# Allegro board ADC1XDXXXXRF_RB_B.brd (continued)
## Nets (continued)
N16907762: C179.1 R90.2 R91.2 U13.8(FB2)
N16907804: C165.2 U13.9(BST2)
N16911166: C154.1 U12.17(VREGVCO)
N16911176: C321.1 U12.21(FOUT)
N16911178: C154.2 R78.2
N16911299: C155.2 U12.18(VREFVCO)
N16911375: C142.2 R70.1
N16911379: C142.1 U12.28(VREGPLL2)
N16911437: C143.1 U12.36(VREGDIG)
N16911467: C140.2 U12.32(OSCIN*)
N16911489: C149.2 U12.6(VREGBUF)
N16911507: C147.2 U12.26(VREGPLL1)
N16911511: C147.1 R71.1
N16915941: R66.2 R67.1 Y3.3(OUT)
N16917380: R73.1 U12.25(FLOUT)
N16922604: C343.2 T2.2
N16954745: C223.1(POS) C226.2 L12.1 R118.1 U20.5(OUTPUT)
N16954757: C227.1 U20.1(BYPASS)
N16954773: C226.1 R117.2 R118.2 U20.6(ADJ)
N17041129: R18.2 U2.99(RESET_N) U3.3(RESET_N)
N17122999: R20.2 U4.1(A0)
N17127467: R16.1 U2.85(PA3/WU2)
N17138281: C64.1(POS) C65.1 C66.1 L1.1 U2.10(AVCC1) U2.17(AVCC2)
N17209995: J12.2(A) L9.2
N17221364: C157.1(POS) L4.1 R99.2 SW2.2
N17237535: LD11.2(CATHODE) U2.82(PA0/INT0_N)
N17238039: LD11.1(ANODE) R142.1
N17247885: LD10.1(ANODE) R99.1
N17271500: C186.1 U15.1(BYPASS)
N17271514: C185.1 R97.2 R98.2 U15.6(ADJ)
N17272516: C230.1(POS) C233.2 L13.1 R125.1 U22.5(OUTPUT)
N17272520: C234.1 U22.1(BYPASS)
N17272540: C233.1 R124.2 R125.2 U22.6(ADJ)
N17383940: C70.1 U2.11(XTALOUT) Y1.1
N17383990: C71.1 U2.12(XTALIN) Y1.2
N17384219: TP2.1 U2.1(CLKOUT)
N17400918: R92.2 U23.20(RT)
N17401691: R93.2 U23.4(COMP)
N17402468: C235.1 U23.1(SS/TRK)
N17411980: C236.1 R93.1
N17414023: SW1.1 U3.4(MR_N)
N17421515: C237.1 U23.18(VCC)
N17425568: R94.2 R95.2 U23.2(FB)
N17434478: C238.2 D1.2(CATHODE) D5.2(CATHODE) L7.1 U23.7(SW1) U23.8(SW2) U23.13(SW3) U23.14(SW4)
N17462336: C197.1 C239.1(POS) L7.2 L8.1 R94.1
N17658689: C268.1 U1.K2(VBIASI2)
N17658690: C79.1 U1.M4(VBIASQ2)
N17663170: C73.1 U1.L2(VBIASQ1)
N17675090: C72.1 U1.J4(VBIASI1)
N17676120: TP1.1 U1.B1(VBG)
N17676520: R12.1 U1.C3(REXT+)
N17676524: R12.2 U1.D3(REXT-)
N17676530: R7.1 U1.C1(RTRIM+)
N17676534: R7.2 U1.D2(RTRIM-)
N17751700: J21.1 L9.4
N17752133: J21.2 SW2.3
N17824195: J12.1(C) L9.1
N17846912: R9.2 U1.U3(PDI)
N17848835: R25.2 U1.V3(PDQ)
N17849798: R2.2 U1.Y3(FSR)
N17850762: R3.2 U1.W4(DDRPHASE)
N17851727: R4.2 U1.B3(ECE)
N17852693: R5.2 U1.V4(CALDLY)
N17853660: R6.2 U1.V5(DES)
N17854628: R8.2 U1.A4(TPM)
N18005197: J22.2 L14.1
N18092594: R13.1 U2.113(PE5/INT6)
N18092628: R14.1 U2.112(PE4/RXD1OUT)
N18102458: R17.1 U2.77(PC5/GPIFADR5)
N18106734: C201.1 C247.1 C248.1 J22.1 R149.1 U17.4(OUT)
N18113304: C247.2 R149.2 R150.1 U17.5(ADJ)
N18167238: C215.1(POS) C219.2 L11.1 R112.1 U19.5(OUTPUT)
N18167362: C220.1 U19.1(BYPASS)
N18167368: C219.1 R111.2 R112.2 U19.6(ADJ)
N18175634: C267.1 R120.2 R121.2 R122.2 U21.1(VCC) U21.3(EN) U29.5(VOUT)
N18175719: J14.1 U21.6(FLAG1)
N18175721: J14.3 U21.5(FLAG2)
N18175723: J14.5 U21.4(FLAG3)
N18175776: C266.1 U29.4(BYPASS)
N18581058: FMC.J39 FMC.K40 J157.1
N18581183: FMC.E39 FMC.F40 FMC.G39 FMC.H40 J157.2
N19099019: R127.2 U1.A5(NDM)
N19100077: R128.2 U1.D6(CAL)
N19255100: J19.3 U24.2(D+)
N19265006: R131.1 U24.7(Q+)
N19266083: R129.1 U24.6(Q-)
N19380996: U24.3(D-) U24.4(VBB)
N20455301: R83.3 U14.12(CLK)
N20455532: R83.1 U14.9(CLKOUT)
N21058732: R44.1 U5.AD19(IO_L25P_CC_SM7_LC_7)
N21059382: R45.1 U5.AC19(IO_L25N_CC_SM7_LC_7)
N21060033: R46.1 U5.AA19(IO_L26P_SM6_7)
N21060685: R26.1 U5.AA20(IO_L26N_SM6_7)
N21061338: R27.1 U5.Y17(IO_L27P_SM5_7)
N21061992: R28.1 U5.AA17(IO_L27N_SM5_7)
N21062647: R113.1 U5.AB20(IO_L28P_7)
N21063303: R114.1 U5.AC20(IO_L28N_VREF_7)
N21827542: R136.1 U25.7(Q+)
N21827567: R134.1 U25.6(Q-)
N21827581: J26.3 U25.2(D+)
N21832116: U25.3(D-) U25.4(VBB)
N21933562: R126.1 U8.9(A0)
N23828730: R53.2 U5.AD12(IO_L8P_GC_CC_LC_4)
N200444310: DCLK_LOCKED.1(ANODE) R54.1
N200444470: ECM_ENABLED.1(ANODE) R55.1
N200445120: R49.1 TRIGGER_ARMED.1(ANODE)
N200445200: ADC_CALIBRATION.1(ANODE) R48.1
N200445280: OVER-RANGE_Q-CH.1(ANODE) R51.1
N200445360: OVER-RANGE_I-CH.1(ANODE) R50.1
N200445600: ADC_POWER.1(ANODE) R47.1
N200446320: FPGA_OPERATIONAL.1(ANODE) R52.1
N210916850: R115.1 RCOUT1/2_ENABLED.1(ANODE)
N1739169316: C238.1 U23.17(BOOT)

Pads without a net: FMC A2 A3 A6 A7 A10 A11 A14 A15 A18 A19 A22 A23 A26 A27 A30 A31 A34 A35 A38 A39 B1 B4 B5 B8 B9 B12 B13 B16 B17 B20 B21 B24 B25 B28 B29 B32 B33 B36 B37 B40 C2 C3 C6 C7 C30 C31 C34 C35 C37 C39 D4 D5 D17 D18 D29 D30 D31 D32 D33 D34 D35 D36 D38 D40 E12 E13 E15 E16 E18 E19 E33 E34 E36 E37 F16 F17 F19 F20 F34 F35 F37 F38 G2 G3 G19 G33 G34 G36 G37 H1 H4 H5 H37 H38 J2 J3 J15 J16 J18 J19 J21 J22 J33 J34 J36 J37 K1 K4 K5 K16 K17 K19 K20 K22 K23 K34 K35 K37 K38; FMC1 1; FMC2 1; J12 3; J15 10; J17 10; SW2 1 4 5; U1 C7 D1 D7 E3 F4 U7 W3; U2 6 7 8 9 14 15 16 28 29 30 31 34 38 39 83 106; U5 A11 A12 A18 AA18 AA23 AA24 AA26 AB18 AB21 AB22 AB23 AB24 AB25 AB26 AC18 AC21 AC22 AC23 AC25 AC26 AD7 AD20 AD21 AD22 AD23 AD26 AE18 AE20 AE21 AE23 AF19 AF20 B6 B12 B13 B14 B15 B18 C6 C11 C14 C15 C16 C19 D1 D2 D11 D12 D13 D14 D15 D16 D18 E2 E3 E13 E14 E17 E18 F15 F17 F18 G11 G20 H12 H20 K20 L3 L4 L8 L19 M8 M19 N19 P19 P20 R7 R8 R19 R20 T1 T19 U1 U20 V20 V21 V22 W13 W19 W20 W21 W22 W23 W24 W25 W26 Y14 Y18 Y19 Y20 Y21 Y22 Y23 Y24 Y25 Y26; U6 2 4 6; U7 2 4 6; U8 1 3 4; U12 2 4 5 7 12 13 14 15 29 35 39; U14 1 3 5 10 14 16 18 25 26 27 29 32 33 35 37 39 40 41 42 43 44 47 48; U15 2 7; U16 5 19; U18 2 7; U19 2 7; U20 2 7; U22 2 7; U23 3; U24 1; U25 1; Y2 1; Y3 1

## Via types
v1: diameter 0.61, hole 0.254, TOP to BOTTOM, 1340 vias
v2: diameter 0.61, hole 0.33, TOP to BOTTOM, 569 vias
v3: diameter 0.55, hole 0.25, TOP to BOTTOM, 351 vias
v4: diameter 0.508, hole 0.254, TOP to BOTTOM, 41 vias

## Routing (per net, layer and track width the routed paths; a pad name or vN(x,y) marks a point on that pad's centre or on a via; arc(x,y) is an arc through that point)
1V2VCC_INT: length 58.2
  TOP w0.102: v1(130.72,87.74) 130.22,88.23 U5.U17 ; v1(130.72,87.74) U5.U18 131.22,88.25 ; v1(130.72,87.74) U5.V17 130.21,87.24 v1(129.72,87.74) ; v1(123.71,88.75) 123.22,88.25 U5.U10 ; v1(123.71,88.75) 123.71,88.76 U5.T10 ; v1(123.71,88.75) 124.21,89.25 U5.T11 ; v1(122.71,88.75) 123.21,88.24 U5.U10 ; v1(122.71,88.75) 123.21,89.25 ; v1(122.71,88.75) 122.22,88.25 U5.U9 ; v1(122.71,88.75) 122.22,89.24 U5.T9 122.22,89.26 v1(122.71,89.75) 123.21,89.25 ; v1(123.71,87.74) 123.22,87.25 U5.V10 ; v1(123.71,87.74) 123.71,87.75 U5.U10 ; v1(123.71,87.74) 124.21,87.24 U5.V11 ; 123.21,94.24 v1(122.71,93.75) 122.22,94.24 U5.L9 122.22,94.26 v1(122.71,94.75) ; 123.21,94.24 U5.L10 123.71,93.76 v1(123.71,93.75) 124.21,94.24 U5.L11 124.22,94.24 v1(124.71,93.75) 125.21,93.25 U5.M12 ; 123.21,94.24 123.21,94.25 v1(122.71,94.75) ; v1(122.71,95.75) 123.21,95.26 123.21,95.24 ; v1(122.71,95.75) 122.22,95.26 U5.K9 122.22,95.24 v1(122.71,94.75) ; v1(122.71,95.75) 123.21,96.25 U5.J10 ; v1(130.73,88.75) 130.72,88.75 U5.U17 ; v1(130.73,88.75) 130.23,89.25 U5.T17 129.72,89.75 v1(129.72,89.75) 129.22,89.25 U5.T16 129.21,89.25 v1(128.71,89.75) 128.22,90.24 U5.R15 ; v1(130.73,88.75) 131.22,89.24 U5.T18 131.72,88.75 v1(131.72,88.75) 131.23,88.25 131.22,88.25 ; v1(130.73,88.75) 131.22,88.25 ; U5.U17 v1(129.72,87.74) ; v1(122.71,94.75) 123.21,95.24 ; v1(129.72,87.74) U5.V16 129.21,87.24 v1(128.71,87.74) ; v1(130.72,94.75) 131.21,95.24 U5.K18 v1(130.72,95.75) ; v1(130.72,94.75) U5.L18 131.21,94.24 v1(130.72,93.75) U5.L17 ; v1(130.72,94.75) U5.K17 ; v1(130.72,94.75) 130.72,94.74 U5.L17 ; U5.L17 130.21,94.24 v1(129.72,93.75) U5.L16 129.21,94.24 v1(128.71,93.75) 128.22,93.26 U5.M15 128.22,93.25 v1(127.71,93.75) ; U5.K10 123.21,95.24 ; v1(130.72,95.75) 130.72,95.74 U5.K17 ; v1(130.72,95.75) U5.J17 130.21,96.25 v1(129.72,95.75) ; 123.21,89.25 U5.T10 ; v1(128.71,96.75) U5.J16 v1(129.72,95.75) ; U5.T11 123.72,89.75 v1(123.71,89.75) 123.71,89.74 U5.T10 ; U5.T11 124.22,89.26 v1(124.71,89.75) 125.21,90.24 U5.R12 ; U5.K17 v1(129.72,95.75) ; v1(124.71,95.75) 124.22,96.24 U5.J11
  TOP w0.762: L8.2 v2(78.72,144.47) ; L8.2 79.98,143.18 v2(79.98,143.17) 79.98,143.16 C243.1 ; L8.2 81.23,144.47 v2(81.24,144.46) ; C243.1 79.98,140.44 v2(79.98,140.44) 79.98,140.44 C184.1 ; C243.1 v2(78.68,141.56) ; C184.1 v2(78.77,139.42) ; C184.1 v2(79.98,138.22)
  BOTTOM w0.305: C253.2 v1(130.72,87.74)
  vias: v1(106.15,123.06) v1(106.15,120.98) v1(108.94,123.06) v1(108.94,120.98)
1V8IO: length 118.7
  TOP w0.102: U5.AA22 135.72,83.74 v1(135.72,83.74) ; U5.W18 131.22,86.25 v1(130.72,85.74) 130.22,86.24 U5.W17 130.22,86.25 v1(129.72,85.74) ; U5.W18 131.24,86.25 v1(131.73,86.74) 132.22,87.23 U5.V19 ; U5.W18 131.22,86.24 v1(131.72,85.74) ; U5.AB19 132.22,83.24 v1(131.72,82.74) ; v1(135.72,79.74) 135.22,80.24 U5.AE22 ; v1(131.72,79.74) 132.23,80.24 U5.AE19 ; U5.AA25 138.22,84.24 v1(138.72,83.74)
  TOP w0.305: U14.4 156.15,45.35 v2(157.64,43.86) ; U14.34 176.51,39.85 C162.1 v2(177.88,39.66) ; U14.15 155.91,39.85 v2(157.64,41.58)
  TOP w0.508: 133.09,161.78 v2(129.87,161.78) C182.1 v2(128.45,160.55) 128.45,159.41 C183.1 ; 133.09,161.78 134.28,161.78 134.61,162.11 134.61,163.41 R98.1 ; 133.09,161.78 C185.2 133.06,163.64 U15.5 ; C183.1 v2(129.47,159.4) ; C183.1 v2(128.46,158.14)
  PWR1 w0.229: J4.16 164.42,147.11 ; J4.16 163,148.52 ; J4.16 164.42,148.52 ; J4.16 162.78,147.82 ; J4.16 163.71,148.74 ; J4.16 163.71,146.89 ; J4.16 163,147.11 ; J4.16 164.64,147.82 ; 168.08,147.11 J4.10 ; J4.10 168.79,146.89 ; J4.10 167.86,147.82 ; J4.10 169.5,147.11 ; J4.10 168.08,148.52 ; J4.10 168.79,148.74 ; J4.10 169.72,147.82 ; J4.10 169.5,148.52 ; 155.38,148.52 J4.25 ; J4.25 156.8,148.52 ; J4.25 156.09,146.89 ; J4.25 155.16,147.82 ; J4.25 156.09,148.74 ; J4.25 157.02,147.82 ; J4.25 156.8,147.11 ; J4.25 155.38,147.11 ; J4.19 161.88,147.11 ; J4.19 161.17,148.74 ; J4.19 160.24,147.82 ; J4.19 160.46,147.11 ; J4.19 161.88,148.52 ; J4.19 160.46,148.52 ; J4.19 162.1,147.82 ; J4.19 161.17,146.89 ; 172.94,147.82 J4.4 ; J4.4 174.58,148.52 ; J4.4 173.87,148.74 ; J4.4 173.16,148.52 ; J4.4 174.58,147.11 ; J4.4 173.87,146.89 ; J4.4 174.8,147.82 ; J4.4 173.16,147.11 ; J4.7 172.04,147.11 ; J4.7 172.26,147.82 ; J4.7 170.4,147.82 ; J4.7 170.62,147.11 ; J4.7 172.04,148.52 ; J4.7 171.33,146.89 ; J4.7 171.33,148.74 ; J4.7 170.62,148.52 ; J4.13 166.96,148.52 ; J4.13 165.54,147.11 ; J4.13 165.32,147.82 ; J4.13 166.25,146.89 ; J4.13 167.18,147.82 ; J4.13 165.54,148.52 ; J4.13 166.96,147.11 ; J4.13 166.25,148.74 ; J4.22 158.63,148.74 ; J4.22 159.34,148.52 ; J4.22 159.56,147.82 ; J4.22 158.63,146.89 ; J4.22 157.92,147.11 ; J4.22 159.34,147.11 ; J4.22 157.92,148.52 ; J4.22 157.7,147.82 ; 175.7,147.11 J4.1 ; J4.1 176.41,148.74 ; J4.1 177.12,147.11 ; J4.1 175.48,147.82 ; J4.1 177.12,148.52 ; J4.1 177.34,147.82 ; J4.1 175.7,148.52 ; J4.1 176.41,146.89 ; 152.84,148.52 J4.28 ; J4.28 152.62,147.82 ; J4.28 154.48,147.82 ; J4.28 154.26,148.52 ; J4.28 152.84,147.11 ; J4.28 153.55,148.74 ; J4.28 154.26,147.11 ; J4.28 153.55,146.89
  BOTTOM w0.305: v1(171.45,94.44) 171.92,94.44 C255.2 ; C256.2 v1(171.45,79.27) ; C254.2 v1(171.45,113.87)
  BOTTOM w0.508: v2(157.64,43.86) C163.1 v2(157.64,41.58)
  BOTTOM w0.61: C362.1 v1(170.57,115.86) ; C363.1 v1(170.57,113.6)
  vias: v1(140.13,81.74) v1(140.13,81)
1V9AC: length 12.9
  TOP w0.102: U1.R4 195.43,102.52 v1(196.06,103.15) 196.7,102.51 U1.R3
  TOP w0.457: J36.2 188.67,143.75 J23.4
  PWR2 w0.356: 188.67,141.81 J23.4 ; J23.4 187.93,142.04 ; J23.4 189.4,143.51 ; J23.4 189.4,142.04 ; J23.4 187.7,142.78 ; J23.4 188.67,143.74 ; J23.4 189.63,142.78 ; J23.4 187.93,143.51
  BOTTOM w0.305: C52.1 194.98,103.15 v1(196.06,103.15)
  BOTTOM w0.457: J36.2 188.67,142.78 J23.4
1V9ANA: length 147.5
  TOP w0.102: v1(194.83,94.23) 195.43,93.63 U1.H4 ; U1.F1 199.24,91.08 v1(199.86,90.46) 199.24,89.83 U1.E1 ; U1.U9 189.08,105.05 v1(189.74,104.39) 190.35,105.01 U1.U8 190.35,105.05 v1(191.01,104.39) ; v1(192.26,86.64) 192.89,86.01 U1.B6 ; v1(194.83,99.38) 195.43,99.97 U1.N4 ; U1.A6 v1(192.26,84.11) ; v1(190.94,89.14) U1.D8 190.27,88.54 v1(189.68,89.14) 189.09,88.54 U1.D9 ; U1.W6 v1(193.52,108.23) U1.Y6 ; U1.A2 197.97,84.73 198.59,84.1 v1(198.59,84.16) ; v1(199.95,101.8) U1.R1 199.85,103.13 v1(199.91,103.13) 199.25,103.78 U1.T1 ; U1.Y2 197.97,108.87 198.62,109.52 v1(198.62,109.56)
  TOP w0.457: J38.2 186.13,142.78 J23.6
  PWR1 w0.356: J23.6 186.13,143.74 ; J23.6 185.71,141.82 ; J23.6 186.86,142.04 ; J23.6 186.86,143.51 ; J23.6 185.39,143.51 ; J23.6 187.09,142.78 ; J23.6 185.39,142.04 ; J23.6 186.13,141.81
  BOTTOM w0.305: v1(198.59,84.16) 198.61,84.15 C1.1 ; v1(198.62,109.56) 198.59,109.58 C2.1 ; v1(193.52,108.23) 193.52,107.15 C6.1 ; v1(190.94,89.14) v1(189.68,89.14) 189.68,90.01 C5.1 ; v1(199.95,101.8) 199.93,101.78 C3.1 199.36,102.07 199.36,102.59 v1(199.91,103.13) ; v1(189.74,104.39) 190.37,103.76 190.72,103.76 C4.1 191.01,104.39 v1(191.01,104.39) ; C7.1 200.33,90.46 v1(199.86,90.46)
  BOTTOM w0.457: J23.6 186.13,142.78 J38.2
  BOTTOM w0.635: v1(198.07,78.92) v1(198.07,78.18) 195.1,75.21 195.1,51.64 173.41,29.95 130.68,29.95 127.66,26.92 C323.1 126.09,26.92 J44.1
1V9AT: length 46.5
  TOP w0.102: v1(199.95,93.05) 199.26,92.35 U1.G1 199.24,92.36 v1(198.54,93.05) 197.97,93.62 U1.H2 197.97,93.63 v1(197.32,94.27) 196.7,94.89 U1.J3 ; U1.C6 192.89,87.28 v1(193.6,87.93) ; U1.K3 196.7,96.23 v1(197.27,96.8) 196.7,97.38 U1.L3 ; U1.M3 196.7,98.72 v1(197.31,99.33) 197.95,99.97 U1.N2 197.99,99.97 v1(198.58,100.57) 199.24,101.23 U1.P1 199.25,101.24 v1(199.92,100.57) ; U1.G3 196.7,92.35 v1(196.07,92.98) 196.05,92.98 U1.G4 195.43,92.36 v1(194.81,92.97) ; U1.P3 196.68,101.24 v1(196.1,100.66) 196.01,100.66 U1.P4 195.41,101.24 v1(194.83,100.66)
  TOP w0.457: J23.2 191.21,143.72 191.21,143.72 J34.2
  PWR1 w0.356: 190.47,143.51 J23.2 ; J23.2 191.94,142.04 ; J23.2 191.21,141.81 ; J23.2 192.17,142.78 ; J23.2 190.47,142.04 ; J23.2 191.94,143.51 ; J23.2 190.24,142.78 ; J23.2 191.21,143.74
  BOTTOM w0.305: v1(198.58,100.57) 199.23,99.92 199.64,99.92 C36.1 199.92,100.57 v1(199.92,100.57) ; C39.1 197.32,94.27 v1(197.32,94.27) ; v1(198.54,93.05) 199.24,93.05 ; 199.24,93.05 v1(199.95,93.05) ; 199.24,93.05 C34.1 ; C40.1 197.32,99.32 v1(197.31,99.33) ; v1(194.83,100.66) 195.39,100.1 195.83,100.1 C38.1 196.13,100.63 v1(196.1,100.66) ; v1(193.6,87.93) 192.32,87.93 C41.1 192.3,92.25 193.37,93.32 194.47,93.32 v1(194.81,92.97) 195.49,93.65 195.78,93.65 C35.1 196.08,92.98 v1(196.07,92.98)
  BOTTOM w0.457: J23.2 191.21,142.78 J35.2
1V9DR: length 49.6
  TOP w0.102: v1(182.1,104.42) U1.U15 181.46,105.05 v1(180.83,104.42) 180.19,105.05 U1.U16 ; v1(185.89,104.41) 186.54,105.05 U1.U11 ; U1.D15 181.47,88.54 v1(182.14,89.22) ; v1(179.54,94.28) 178.93,94.89 U1.J17 ; U1.R20 175.11,102.51 v1(174.48,101.88) ; U1.C18 v1(178.28,87.91) U1.D17 v1(179.55,89.18) ; v1(181.45,110.35) 181.46,110.34 U1.Y15 ; U1.Y11 186.54,109.86 ; U1.D11 186.54,88.54 v1(185.91,89.17) ; v1(187.16,84.12) 186.55,84.73 U1.A11 ; v1(180.86,84.14) 181.46,84.73 U1.A15 ; v1(179.53,101.9) 178.92,102.51 U1.R17 179.53,103.13 v1(179.53,103.17) U1.T17 ; U1.J20 175.11,94.89 v1(174.5,94.28)
  TOP w0.152: 186.54,109.86 186.3,110.1 v1(185.19,110.1)
  TOP w0.457: J23.10 181.05,142.78 J42.2
  PWR1 w0.356: J23.10 181.78,143.51 ; J23.10 181.78,142.04 ; J23.10 180.31,143.51 ; J23.10 182.01,142.78 ; J23.10 181.05,143.74 ; J23.10 181.05,141.81 ; J23.10 180.08,142.78 ; J23.10 180.31,142.04
  BOTTOM w0.305: v1(182.14,89.22) 182.14,90.28 C26.1 ; C30.1 173.6,93.38 173.6,94.28 ; 173.6,94.28 C255.1 ; 173.6,94.28 v1(174.5,94.28) ; v1(181.45,110.35) 180.53,111.26 180.53,111.4 C21.1 ; v1(174.48,101.88) 173.56,100.96 173.56,100.44 C20.1 ; C254.1 v1(174.45,113.87) ; C22.1 182.11,104.41 v1(182.1,104.42) 182.09,104.42 v1(180.83,104.42) ; C29.1 v1(185.91,89.17) ; v1(185.19,110.1) 185.15,110.14 C18.1 ; C19.1 v1(185.89,104.41) ; v1(179.53,101.9) 179.59,101.85 C23.1 180.34,102.05 180.34,102.36 v1(179.53,103.17) ; C256.1 v1(174.45,79.27) ; v1(187.16,84.12) 186.89,83.85 186.89,83.46 C28.1 ; v1(180.86,84.14) 180.84,84.11 C27.1 ; C24.1 180.2,94.11 179.72,94.11 v1(179.54,94.28)
  BOTTOM w0.457: J23.10 181.05,142.78 J42.2
1V9ENC: length 18.3
  TOP w0.102: v1(190.99,109.5) 190.35,108.86 U1.Y8 ; U1.B9 189.71,86.64 ; 189.71,86.64 U1.C8 ; 189.71,86.64 v1(189.71,86.66) ; U1.V8 v1(189.7,106.97) U1.W9 ; v1(190.98,84.1) U1.A8
  TOP w0.457: J23.8 183.59,142.78 J40.2
  PWR1 w0.356: J23.8 184.55,142.78 ; J23.8 182.85,143.51 ; J23.8 183.59,141.81 ; J23.8 183.59,143.74 ; J23.8 184.32,143.51 ; J23.8 182.62,142.78 ; J23.8 184.32,142.04 ; J23.8 182.85,142.04
  BOTTOM w0.305: C48.1 190.99,110.55 v1(190.99,109.5) ; v1(189.7,106.97) 189.7,106.97 189.7,107.45 C49.1 ; C47.1 189.71,85.58 v1(189.71,86.66)
  BOTTOM w0.457: J40.2 183.59,142.78 J23.8
2V5IO: length 232.3
  TOP w0.102: U5.B11 124.22,103.27 v1(124.71,103.76) ; v1(129.72,82.74) 129.22,83.24 U5.AB16 ; U5.H9 122.2,97.24 v1(121.71,96.75) 121.22,96.26 U5.J8 121.21,96.25 v1(120.71,95.75) 121.21,95.24 ; v1(138.69,94.75) 138.69,94.71 U5.L25 ; v1(131.72,102.75) U5.B19 ; U5.E11 124.22,100.26 v1(124.71,100.75) ; v1(123.71,82.74) 124.22,83.25 U5.AB11 ; v1(117.71,103.76) 118.22,103.25 U5.B5 ; 131.21,91.24 v1(130.72,90.75) 131.22,90.24 U5.R18 ; 131.21,91.24 131.21,91.25 v1(130.72,91.75) 131.21,92.25 U5.N18 131.72,92.74 v1(131.72,92.75) 131.22,93.24 U5.M18 131.22,93.25 v1(131.72,93.75) ; 131.21,91.24 U5.P18 ; v1(114.72,88.75) U5.T2 ; v1(132.72,88.75) 132.22,88.25 U5.U19 ; U5.H19 v1(132.71,96.75) 132.71,96.74 U5.J19 132.22,96.25 v1(131.72,96.75) ; U5.H19 132.21,97.24 v1(131.72,96.75) ; U5.H19 132.22,97.25 v1(131.72,97.75) 131.72,97.74 U5.H18 131.22,97.24 v1(131.72,96.75) ; U5.E16 129.22,100.25 v1(128.71,100.75) ; U5.F25 138.22,99.25 v1(138.73,99.75) ; U5.E19 132.22,100.26 v1(132.72,100.75) ; v1(129.72,103.76) 129.22,103.26 U5.B16 ; v1(120.71,87.74) 121.21,88.24 U5.U8 ; v1(135.72,88.75) 135.74,88.75 135.56,88.92 135.56,88.93 135.24,89.25 U5.T22 ; U5.T25 138.22,89.25 v1(138.72,88.75) ; U5.K8 121.21,95.24 ; 121.21,95.24 v1(120.71,94.74) ; v1(132.72,94.75) 132.22,95.24 U5.K19 ; v1(117.71,93.75) 118.2,94.24 U5.L5 ; v1(125.71,96.75) 125.22,96.26 U5.J12 125.22,96.25 v1(124.71,96.75) 124.22,97.24 U5.H11 124.22,97.24 v1(123.71,97.75) 123.22,97.26 U5.H10 ; U5.N1 114.2,92.25 v1(113.71,91.75) ; v1(134.72,103.76) 134.72,103.75 135.22,103.25 U5.B22 ; U5.R9 122.22,90.24 v1(121.78,90.75) 122.22,91.18 U5.P9 122.22,91.26 v1(122.71,91.75) 122.71,91.75 U5.N9 122.22,92.26 v1(122.71,92.75) 122.22,93.24 U5.M9 ; v1(120.71,100.75) 121.22,100.24 U5.E8 ; U5.F2 v1(114.72,98.75) ; 124.21,86.25 124.21,86.24 v1(123.71,85.74) 123.22,86.23 U5.W10 123.22,86.25 v1(123.71,86.74) 124.21,86.25 ; 124.21,86.25 U5.W11 ; U5.W16 129.21,86.25 v1(128.71,86.74) 128.22,87.23 U5.V15 128.22,87.24 v1(127.71,86.74) ; v1(139.72,90.75) 139.23,91.24 U5.P26 ; v1(135.71,98.75) 135.22,99.24 U5.F22 ; U5.AF17 130.22,79.21 v1(130.72,78.71) ; v1(117.72,88.75) U5.T5 ; U5.L22 v1(135.72,94.75) ; U5.B8 121.22,103.25 v1(120.71,103.76) ; v1(114.7,93.75) 115.2,94.24 U5.L2 ; 129.22,97.24 v1(129.72,96.75) 130.21,97.24 U5.H17 v1(129.72,97.75) U5.H16 129.22,97.24
  TOP w0.203: U15.8 130.67,167.86 v1(130.65,168.78)
  TOP w0.254: U5.F5 118.22,99.25 v1(117.72,98.75)
  TOP w0.305: R33.1 R37.1 R36.1 R35.1 R32.1 136.45,34.22 136.45,34.22 v2(136.45,34.54) ; R104.1 R87.1 R86.1 156.15,53.17 v2(156.16,53.17) ; R91.1 113.33,184.08 v2(113.33,184.08) ; C252.2 v1(110.94,87.74) ; C251.2 v1(111.43,89.75) ; C249.2 v1(110.61,95.75) ; C250.2 v1(110.94,92.75) v1(112.21,92.75) C120.1 112.25,91.75 v1(113.71,91.75)
  TOP w0.381: C325.2 v1(111.77,98.75) ; C326.2 v1(111.53,100.75) ; C327.2 v1(111.28,102.76)
  TOP w0.508: C180.1 120.62,162.52 v2(120.62,162.51) ; C180.1 119.31,163.64 v2(119.3,163.65) ; C180.1 121.81,163.64 v2(121.81,163.64) 121.81,163.64 C181.1 ; U15.4 C181.1 ; C181.1 122.76,162.62 v2(122.75,162.61)
  TOP w0.762: C170.1 116.98,166.16 v2(116.99,166.16) ; C170.1 115.79,167.17 v2(115.78,167.18) ; C170.1 116.98,167.95 v2(116.95,167.98) 116.97,168 C169.1 ; L6.2 116.97,170.54 v2(116.96,170.54) 116.97,170.53 C169.1 ; C169.1 115.6,168.98 v2(115.57,169.01)
  BOTTOM w0.14: C124.1 119.71,89.7 119.26,89.25 U5.T5 v1(117.72,88.75) ; v1(135.72,88.75) 135.22,88.24 135.22,87.28 C118.1 ; C93.1 134.84,105.66 134.24,105.07 134.24,104.24 v1(134.72,103.76) 135.22,104.25 C93.1
  BOTTOM w0.152: C274.1 139.23,100.25 v1(138.73,99.75)
  BOTTOM w0.203: v2(122.75,162.61) 122.75,163.03 128.5,168.79 130.65,168.79 v1(130.65,168.78)
  BOTTOM w0.305: v2(116.96,170.54) 113.33,174.18 v2(113.33,184.08) 113.33,185.02 C179.2 ; C274.1 v1(140.59,100.75) ; C259.1 v1(182.07,92.99) ; v1(136.53,63.65) 123.95,63.65 122.53,65.07 J156.2 J155.2 ; C272.1 v1(123.71,97.75) ; C123.1 v1(117.71,93.75) ; C119.1 v1(138.69,94.75) ; C258.1 v1(182.08,100.6)
  BOTTOM w0.381: C125.1 v1(120.71,94.74) 120.71,95.74 C97.1 v1(121.71,96.75) ; v1(138.72,88.75) 138.73,88.75 C295.1
  BOTTOM w0.406: v1(164.52,94.18) C364.1 ; C365.1 v1(183.31,115.44)
  BOTTOM w0.61: C257.1 v1(173.18,109.5)
  vias: v1(112.7,99.75) v1(112.66,93.75) v1(114.35,128.24) v1(114.35,126.16) v1(117.14,128.24) v1(117.14,126.16) v1(177.01,85.37)
3V0PLL: length 19.4
  TOP w0.254: v1(198.27,156.24) 197.66,156.24 197.19,155.76 U12.22 ; U12.27 196.11,158.26 196.37,158.51 196.37,160.81 C145.2 ; C144.1 189.38,158.26 U12.1 ; U12.16 194.29,152.18 C156.2
  TOP w0.508: C144.1 v1(188.82,156.87) ; C156.2 v1(192.81,151.59) ; C145.2 v1(197.36,161.01) ; R65.1 v1(203.1,166.9)
  TOP w0.889: L13.2 v1(169.33,194.54) C231.1 v1(169.33,192.71) C232.1 v1(169.33,190.55) TP15.1
3V3IO: length 110.2
  TOP w0.102: U5.AB8 121.21,83.25 v1(120.71,82.74) ; U5.W8 121.22,86.23 v1(121.71,85.74) C291.1 U5.W9 122.22,86.25 v1(122.71,86.74) ; v1(120.71,79.74) 120.72,79.74 U5.AE8 ; U5.V12 125.22,87.25 v1(125.71,87.74) ; v1(123.71,79.74) 123.72,79.74 U5.AE11 ; v1(121.71,87.74) 121.22,87.25 U5.V8 ; U5.AA2 115.21,84.24 v1(114.7,83.74) ; v1(128.71,80.74) 128.22,81.23 U5.AD15 ; U5.AE5 118.22,80.24 117.73,79.76 ; v1(127.71,95.75) 128.21,96.25 U5.J15 ; v1(117.71,83.74) 118.21,84.24 U5.AA5
  TOP w0.14: v1(134.68,70.41) 134.69,70.4 R38.1
  TOP w0.203: v1(117.73,78.54) 117.73,79.76
  TOP w0.305: C265.1 v1(61.11,77.72) ; U14.30 175.41,37.85 175.68,37.57 176.11,37.57 C172.1 v2(177.8,36.99) ; R88.1 104.97,184.02 v2(104.98,184.02) ; v2(177.91,45) 177.9,45.01 C173.1 176.68,45.02 175.87,45.02 175.54,45.35 U14.45 ; R34.1 v1(114.94,113.59) ; C263.1 v1(78.66,85.8) ; R85.1 v2(148.31,47.67) ; C252.1 v1(107.94,87.74) ; v2(154.71,33.03) 154.72,33.03 C171.1 154.72,34.27 U14.24 ; v2(146.42,44.38) 146.41,44.38 146.05,44.02 R81.1 ; C251.1 v1(108.43,89.75) ; R40.1 v1(114.88,115.4) ; v2(156.41,43.5) 156.26,43.35 U14.8 ; v2(177.91,42.31) 177.9,42.32 C174.1 176.69,42.32 175.89,42.32 175.41,41.85 U14.38 ; R29.1 v1(114.94,111.99) ; C262.1 v1(76.23,91.75) ; C250.1 v1(108.8,91.75) ; v1(107.73,96.74) 107.73,96.48 C249.1
  TOP w0.381: C327.1 v1(108.03,102.76) ; C326.1 v1(108.28,100.75) ; C325.1 v1(108.78,98.75)
  TOP w0.508: C168.1 102.59,168.99 v2(102.59,170.2) 102.59,170.2 L5.1 ; C168.1 102.57,168.95 v2(102.57,167.94) 102.58,167.94 C167.1 101.35,167.19 v2(101.34,167.18) ; C168.1 101.35,168.98 v2(101.34,168.97) ; C78.1 v1(119.66,70.21) ; C78.1 v1(118.72,69.14) ; C78.1 Y2.4 ; C74.1 J6.1
  TOP w0.762: v2(102.56,166.31) 102.58,166.33 C167.1 ; v2(106.39,172.71) 106.37,172.69 L5.1 98.87,172.69 v2(98.87,172.69)
  PWR2 w0.229: 149.58,54.63 J6.1 ; J6.1 148.46,56.87 ; J6.1 150.7,56.87 ; J6.1 150.14,56.87 ; J6.1 148.46,55.75 ; J6.1 148.46,54.63 ; J6.1 149.58,56.87 ; J6.1 149.02,54.63
  BOTTOM w0.203: v4(199.32,47.4) R54.2 R51.2 R49.2 R47.2 R48.2 R50.2 R52.2 R55.2
  BOTTOM w0.305: C166.1 155.53,43.5 v2(156.41,43.5) ; C178.2 104.98,185.02 v2(104.98,184.02) 104.98,184.02 106.39,182.61 v2(106.39,172.71) ; C110.1 v1(117.73,78.54) ; R55.2 R115.2 v2(199.32,28.42)
  BOTTOM w0.508: C108.1 v1(114.7,83.74) ; v1(114,73.13) v1(114,74.08)
  vias: v1(59.25,88.6) v1(83.5,96.6) v1(117.71,105.76) v1(119.56,106.63)
3V3USB: length 59.9
  TOP w0.152: R19.2 v4(96.52,14.05) ; R20.1 v4(86.59,13.77) ; R21.2 v4(103.65,11.28)
  TOP w0.203: U3.5 123.99,9.38 C67.1 ; v2(97.23,22.1) 97.23,23.51 U2.64 ; R18.1 v1(126.65,14.44) ; 100.58,33.27 v2(100.72,33.13)
  TOP w0.305: U2.26 v2(81.39,31.27) C63.1 80.12,30.17 v2(80.11,30.16) ; C57.1 v2(86.34,21.8) 86.73,22.18 U2.43 ; U2.81 100.58,33.27 ; U2.48 89.23,24.8 v2(88.84,25.19) ; v2(125.76,8.46) C67.1 ; U2.2 v2(81.35,43.27) ; U2.107 95.23,44.1 v2(94.97,43.84) ; v2(100.6,43.27) U2.101 ; C58.1 96.33,21.79 96.65,22.1 97.22,22.1 v2(97.23,22.1) ; R15.2 v1(105.26,37.51) ; v2(97.21,42.77) U2.100 ; v1(119.88,19.22) 119.82,19.15 R142.2 ; U2.68 v2(97.47,26.77)
  TOP w0.508: L1.2 v2(69.01,53.78) ; L1.2 67.58,52.32 v2(67.57,52.33) ; L1.2 v2(69.01,50.91) ; v2(93.07,14.45) 93.05,14.44 C68.1 U4.8
  TOP w0.762: C217.1 66.01,48.31 v2(66,48.31) 66.01,48.3 C216.1 ; C217.1 67.46,49.59 v2(67.46,49.59) ; C217.1 v2(66.01,51.27) L11.2 66.01,52.33 v2(67.57,52.33) ; C216.1 67.13,47.11 v2(67.13,47.11) ; C216.1 66.01,45.76 v2(66,45.75)
  BOTTOM w0.508: v2(97.21,42.77) 97.56,42.42 98.69,42.42 C61.1 99.28,42.42 99.74,42.42 v2(100.6,43.27) ; v2(100.72,33.13) 99.79,33.13 C60.1 ; C54.1 v2(81.35,43.27) ; v2(88.84,25.19) 88.88,25.24 C56.1 ; C55.1 v2(81.39,31.27) ; v2(97.47,26.77) 97.61,26.63 97.61,25.87 C59.1 ; C62.1 v2(94.97,43.84)
3V3USI1: length 28.4
  TOP w0.254: C77.1 166.44,56.07 U8.2
  TOP w0.305: U25.8 202.9,177.8 C246.1 202.9,176.84 v2(202.9,176.84) ; U24.8 207.6,123.91 208.23,123.91 208.6,123.54 C245.1 v2(208.6,121.93)
  TOP w0.508: C241.1 v2(169.79,57.18) ; C241.1 v2(171.18,56.06) ; C241.1 C136.1 C77.1
  TOP w0.762: v2(180.59,191.22) C225.1 ; C225.1 v2(181.8,189.87) ; C225.1 v2(181.8,192.62) C224.1 ; C224.1 181.79,193.56 v2(181.79,194.67) 181.8,194.68 L12.2 ; C224.1 v2(180.78,193.55)
  PWR2 w0.229: 186.54,190.52 J13.3 ; J13.3 187.96,191.94 ; J13.3 187.96,190.52 ; J13.3 187.25,192.16 ; J13.3 186.54,191.94 ; J13.3 186.32,191.23 ; J13.3 187.25,190.3 ; J13.3 188.18,191.23
5V0USI1: length 75.7
  TOP w0.508: U20.4 C222.1 C221.1 v1(174.08,198.25) ; U17.1 v1(155.04,181.24)
  TOP w0.762: C211.1 198.24,191.26 v2(198.24,192.6) 198.24,192.61 C210.1 198.24,193.63 v2(198.24,194.73) 198.24,194.73 L3.2 ; C211.1 198.24,189.88 v2(198.24,189.87) ; C211.1 199.5,191.25 v2(199.5,191.25)
  PWR2 w0.229: J13.1 193.26,191.23 ; J13.1 191.62,190.52 ; J13.1 193.04,191.94 ; J13.1 192.33,190.3 ; J13.1 192.33,192.16 ; J13.1 191.4,191.23 ; J13.1 193.04,190.52 ; J13.1 191.62,191.94
  BOTTOM w0.508: 174.08,195.96 189.6,195.96 192.33,193.23 J13.1 ; 174.08,195.96 v1(174.08,198.25) ; 174.08,195.96 174.08,188.85 169.26,184.03 157.83,184.03 v1(155.04,181.24)
GND: length 3008.1
  TOP w0.102: 198.59,85.39 v1(198.59,85.38) ; 130.21,92.25 U5.N17 ; 125.72,89.75 v1(125.71,89.75) ; 125.21,88.24 U5.U12 ; 130.21,91.24 U5.P17
  TOP w0.14: R38.3 v1(131.29,70.41)
  TOP w0.254: v1(127.71,87.74) 128.21,88.24 128.21,88.24 ; v1(127.71,87.74) 127.22,88.23 U5.U14 ; v1(127.71,87.74) 127.22,87.25 U5.V14 127.21,87.24 ; v1(114.7,103.76) 115.19,104.24 U5.A2 ; v1(114.7,103.76) 114.22,103.27 U5.B1 ; v1(114.7,103.76) 115.21,103.25 U5.B2 ; 127.21,92.25 127.21,92.25 v1(126.71,92.75) ; 127.21,92.25 v1(126.71,91.75) ; 127.21,92.25 U5.N14 ; U5.AB15 128.22,83.23 v1(128.71,82.74) ; v1(137.72,81.74) 137.23,81.24 U5.AD24 ; 127.21,93.25 U5.M14 127.22,93.24 v1(127.71,92.75) 127.22,92.26 U5.N14 ; 127.21,93.25 127.21,93.25 v1(126.71,93.75) ; 127.21,93.25 v1(126.71,92.75) ; U5.U14 127.22,88.25 v1(127.71,88.75) ; U5.U14 127.21,88.24 ; v1(125.71,95.75) 126.22,95.24 U5.K13 126.22,95.26 v1(126.71,95.75) ; v1(125.71,95.75) 125.22,95.26 U5.K12 125.21,95.24 v1(124.71,94.75) ; v1(125.71,95.75) 125.72,95.75 U5.J13 126.22,96.24 v1(126.71,95.75) ; v1(128.71,92.75) 129.22,92.25 U5.N16 ; v1(128.71,92.75) 128.71,92.74 U5.N15 ; v1(128.71,92.75) 129.21,93.25 U5.M16 129.22,93.24 v1(129.72,92.75) ; v1(138.72,79.74) 138.23,79.25 U5.AF25 ; v1(138.72,79.74) 138.22,80.24 U5.AE25 ; v1(138.72,79.74) 139.22,80.24 U5.AE26 ; 127.21,90.24 127.21,90.25 v1(126.71,90.75) ; 127.21,90.24 U5.R14 ; 127.21,90.24 v1(126.71,89.75) ; v1(137.73,96.75) 137.22,96.25 U5.J24 ; v1(111.21,90.75) 112.19,90.75 C120.2 112.24,90.75 v1(113.71,90.75) 114.2,91.24 U5.P1 ; v1(118.71,91.75) 119.2,92.25 U5.N6 ; v1(196.6,154.28) 195.95,154.26 U12.19 ; v1(126.71,90.75) 126.22,91.24 U5.P13 ; v1(126.71,90.75) 127.21,91.24 ; v1(126.71,90.75) 126.22,90.25 U5.R13 ; v1(129.72,92.75) 129.22,92.25 U5.N16 ; v1(129.72,92.75) 130.21,93.25 U5.M17 130.22,93.24 v1(130.72,92.75) 130.22,92.25 U5.N17 ; v1(129.72,92.75) 130.21,92.25 130.21,92.25 v1(129.72,91.75) ; U5.K16 129.21,95.24 v1(128.71,94.75) ; U5.K16 v1(129.72,94.75) ; U5.K16 v1(128.71,95.75) 128.22,95.26 U5.K15 128.22,95.24 v1(128.71,94.75) ; v1(121.71,80.74) 122.21,81.24 U5.AD9 ; v1(124.71,82.74) 125.22,83.25 U5.AB12 ; v1(126.71,93.75) 127.21,94.24 U5.L14 ; v1(126.71,93.75) 126.71,93.74 U5.M13 ; v1(126.71,93.75) 126.22,94.24 U5.L13 126.21,94.24 v1(125.71,93.75) 125.72,93.75 U5.M13 ; v1(126.71,88.75) 126.22,89.24 U5.T13 ; v1(126.71,88.75) 127.21,89.25 ; v1(126.71,88.75) 127.21,88.24 ; v1(126.71,88.75) 126.22,88.25 U5.U13 126.22,88.23 v1(126.71,87.74) ; U5.M10 123.22,93.24 v1(123.71,92.75) ; v1(131.72,101.75) U5.C18 ; U12.3 v1(189.87,157.25) ; v1(129.72,90.75) 129.72,90.74 U5.R16 129.22,90.24 v1(128.71,90.75) ; v1(129.72,90.75) 130.21,91.24 130.21,91.25 v1(129.72,91.75) ; v1(129.72,90.75) 130.22,90.24 U5.R17 130.23,90.24 v1(130.73,89.75) ; v1(129.72,90.75) 129.72,90.75 U5.P16 ; v1(129.72,91.75) 129.22,91.25 U5.P16 ; v1(129.72,91.75) 129.72,91.75 U5.N16 ; U5.N11 123.72,91.75 v1(123.71,91.75) ; U5.N11 124.22,92.26 v1(124.71,92.75) ; U5.N11 124.21,92.25 v1(123.71,92.75) ; U5.M13 125.72,92.75 v1(125.71,92.75) ; U5.M13 126.22,93.24 v1(126.71,92.75) ; U5.P16 129.21,91.24 v1(128.71,90.75) ; U5.J14 127.21,96.25 v1(126.71,95.75) ; v1(128.71,79.74) 129.21,79.25 U5.AF16 ; v1(128.71,79.74) U5.AE16 129.22,80.23 v1(129.72,79.74) ; v1(128.71,79.74) U5.AF15 ; v1(128.71,79.74) 128.22,80.23 U5.AE15 ; v1(138.72,103.76) 138.23,104.24 U5.A25 ; v1(138.72,103.76) 138.22,103.26 U5.B25 ; v1(138.72,103.76) 139.22,103.25 U5.B26 ; v1(126.71,89.75) 126.22,89.25 U5.T13 ; v1(126.71,89.75) 126.71,89.75 U5.R13 ; v1(126.71,89.75) 127.21,89.25 ; v1(125.71,90.75) 126.22,90.24 U5.R13 ; v1(125.71,90.75) 125.22,91.24 U5.P12 125.21,91.24 v1(124.71,90.75) ; v1(125.71,90.75) 126.21,91.24 U5.P13 ; v1(128.71,88.75) 128.71,88.75 U5.T15 128.21,89.25 v1(127.71,89.75) ; v1(128.71,88.75) 129.21,88.24 U5.U16 129.22,88.25 v1(129.72,88.75) ; v1(128.71,88.75) 128.22,88.25 U5.U15 128.21,88.24 ; v1(126.71,95.75) 127.22,95.24 U5.K14 ; U5.T13 125.72,89.74 125.72,89.75 U5.R13 ; v1(114.71,79.76) 115.22,79.25 U5.AF2 ; v1(114.71,79.76) 115.19,80.24 U5.AE2 ; v1(114.71,79.76) 114.22,80.24 U5.AE1 ; v1(124.71,90.75) 124.22,91.24 U5.P11 124.21,91.24 ; v1(124.71,90.75) 124.22,90.26 U5.R11 124.21,90.24 v1(123.71,90.75) ; v1(126.71,91.75) 126.71,91.74 U5.P13 ; v1(126.71,91.75) 127.21,91.25 127.21,91.24 ; v1(126.71,91.75) 126.71,91.75 U5.N13 ; v1(127.71,88.75) 127.21,89.25 ; v1(127.71,88.75) 128.21,88.24 ; 127.21,89.25 U5.T14 127.22,89.25 v1(127.71,89.75) ; v1(123.71,92.75) 123.72,92.75 U5.M11 124.22,93.24 v1(124.71,92.75) ; v1(123.71,92.75) 123.22,92.26 U5.N10 123.71,91.75 v1(123.71,91.75) ; v1(126.71,92.75) 126.71,92.74 U5.N13 ; v1(124.71,88.75) 125.21,88.24 125.21,88.24 v1(124.71,87.74) 124.71,87.75 U5.U11 124.22,88.25 v1(124.71,88.75) ; v1(124.71,88.75) C134.2 U5.T12 125.22,89.25 v1(125.71,89.75) ; v1(127.71,89.75) 127.71,89.75 U5.R14 ; v1(129.72,79.74) 129.22,79.25 U5.AF16 ; v1(129.72,79.74) U5.AE17 130.22,80.23 v1(130.72,79.74) ; v1(134.72,98.75) 134.22,99.25 U5.F21 ; v1(124.71,92.75) 125.21,92.25 U5.N12 125.22,92.26 v1(125.71,92.75) ; v1(133.72,84.74) 134.22,84.24 U5.AA21 134.22,84.24 v1(134.72,83.74) ; v1(115.7,102.76) 116.22,102.25 U5.C3 ; U5.N13 126.22,92.25 v1(125.71,92.75) ; v1(124.71,94.75) 125.22,94.24 U5.L12 ; v1(124.71,94.75) 124.22,95.24 U5.K11 124.21,95.24 v1(123.71,95.75) ; v1(123.71,91.75) 124.21,91.25 124.21,91.24 ; v1(123.71,91.75) 123.71,91.73 U5.P10 ; U12.20 195.07,154.76 v4(194.82,155.02) ; v4(192.33,158.17) 192.29,158.2 U12.34 192.29,159.6 v1(192.3,159.61) ; v1(115.72,95.75) U5.J3 ; v1(125.71,100.75) 125.22,100.26 U5.E12 ; U5.P14 127.71,91.74 v1(127.71,91.75) 127.71,91.75 U5.N14 ; U5.P14 127.21,91.24 ; U5.P14 127.71,90.75 v1(127.71,90.75) 127.22,90.25 U5.R14 ; v1(128.71,94.75) 128.22,94.26 U5.L15 ; U5.P10 123.22,91.24 v1(123.71,90.75) ; U5.P10 123.21,91.24 v1(122.71,90.75) 123.21,90.24 U5.R10 123.22,90.26 v1(123.71,90.75) ; U5.AF14 127.22,79.23 v1(127.72,78.74) 127.72,78.74 U5.AF15 ; v1(137.72,86.74) 137.72,86.74 U5.V24 ; v1(128.71,90.75) 128.22,91.24 U5.P15 ; U5.P21 v1(134.72,90.75) ; U5.AF16 128.71,78.74 v1(128.71,78.74) 128.22,79.23 U5.AF15 ; U5.AF16 129.22,79.23 v1(129.72,78.74) ; v1(123.71,90.75) 124.21,91.24 ; 127.21,88.24 127.21,88.24 v1(126.71,87.74) ; v1(141.86,79.98) 142.52,80.64 R59.2 ; v1(129.72,84.74) 129.22,85.24 U5.Y16 ; v1(131.72,80.74) 131.22,81.23 U5.AD18 ; v1(126.71,87.74) 127.21,87.24 ; v1(126.71,87.74) 126.22,87.25 U5.V13 126.22,87.23 v1(126.71,86.74) 127.21,87.24 127.21,87.24 ; U5.E15 128.22,100.25 v1(127.71,100.75) ; v4(193.29,158.16) 193.29,158.17 192.84,158.17 192.79,158.21 U12.33 ; v1(118.71,83.74) 119.21,84.24 U5.AA6 ; U5.C9 v1(121.71,102.76) ; U5.AF13 v1(125.71,78.74) ; v1(115.72,86.74) U5.V3 ; v1(125.71,103.76) 126.2,104.24 U5.A13 126.22,104.26 v1(126.71,104.76) 127.22,104.25 U5.A14 ; v1(118.72,98.75) 119.22,99.24 U5.F6
  TOP w0.305: U1.M9 188.45,98.07 v1(188.45,98.07) 188.45,98.06 ; U1.M9 U1.L8 190.35,97.43 v1(190.98,98.06) 190.98,98.06 v1(188.44,100.6) 187.82,99.97 U1.N10 U1.M9 ; U1.M9 189.09,98.7 v1(189.75,99.36) 189.75,99.37 U1.N8 190.36,99.97 v1(190.97,100.59) ; v2(127.24,168.97) 127.23,168.96 C186.2 ; v1(183.87,110.06) 184,109.93 U1.Y13 ; v1(183.37,100.6) U1.N13 184.63,99.34 v1(184.63,99.34) 185.26,98.7 U1.M12 ; U1.M20 175.11,98.7 v1(174.57,98.16) ; U16.21 129.33,189.37 129.33,188.72 ; U1.J13 183.37,95.52 v1(183.36,95.52) 184,96.16 U1.K13 184.63,95.53 184.63,95.53 ; U1.J13 184.63,95.53 ; U1.J13 184,94.89 v1(183.39,94.28) 183.39,94.24 184.01,93.62 ; U1.J13 184.64,94.26 v1(184.64,94.26) ; v1(184.64,94.26) 184.01,93.62 ; v1(184.64,94.26) 185.27,93.63 U1.H12 ; v1(184.64,94.26) 185.27,94.89 U1.J12 ; v1(184.64,95.53) 185.27,94.9 U1.J12 ; v1(184.64,95.53) 184.63,95.53 ; v1(184.64,95.53) 185.27,96.16 U1.K12 185.27,96.16 v1(185.91,95.53) ; U1.A17 178.92,84.73 v1(179.53,84.13) ; U1.M12 U1.N11 186.54,99.98 v1(185.91,100.61) 185.91,100.59 v1(183.37,98.06) U1.L13 U1.M12 ; U1.M12 185.91,98.06 v1(185.91,98.06) 186.53,97.43 U1.L11 ; v1(185.91,95.53) 185.9,95.53 U1.J12 ; v1(185.91,95.53) 186.54,94.9 U1.J11 186.54,94.89 v1(185.91,94.26) ; v1(185.91,95.53) 186.54,96.16 U1.K11 ; C269.2 91,172.18 v2(90.99,172.19) ; 185.9,94.26 185.9,94.26 U1.J12 ; 185.9,94.26 U1.H12 ; 185.9,94.26 v1(185.91,94.26) ; v1(127.71,90.75) 128.21,91.24 ; 128.21,91.24 128.21,91.25 v1(127.71,91.75) 128.21,92.25 U5.N15 127.72,92.75 v1(127.71,92.75) ; 128.21,91.24 U5.P15 ; v1(189.69,109.47) 189.09,108.86 U1.Y9 ; v2(94.24,22.11) 94.23,22.11 U2.58 ; v2(84.69,37.67) 84.59,37.77 U2.13 ; U1.U4 195.43,105.06 v1(196.07,105.7) ; U1.U4 195.43,105.05 v1(194.79,105.69) 194.16,105.05 U1.U5 ; U1.U4 v1(196.07,104.42) ; v1(189.71,84.1) U1.A9 ; U1.R2 197.97,102.55 v1(197.35,103.17) ; 199.86,96.8 199.24,97.43 U1.L1 ; 199.86,96.8 v1(200.27,96.8) ; 199.86,96.8 199.24,96.18 U1.K1 ; 188.45,98.06 U1.M10 187.81,98.7 188.44,99.34 v1(188.44,99.34) 188.45,99.34 U1.N9 189.09,99.97 v1(189.73,100.62) 190.99,99.36 v1(190.99,99.34) 190.35,98.7 U1.M8 189.71,98.07 v1(189.71,98.06) 189.08,97.43 U1.L9 188.45,98.06 ; 188.45,98.06 187.82,97.43 U1.L10 ; v2(159.06,41.58) 156.33,38.85 U14.17 ; C171.2 153.29,34.27 153.29,35.45 153.69,35.85 U14.23 ; 184.01,93.62 U1.H13 184,93.62 v1(183.37,92.99) ; 184.01,93.62 v1(184.64,92.99) 185.27,93.62 U1.H12 ; U1.J9 U1.K8 v1(190.97,95.54) 190.97,95.51 189.72,94.25 ; U1.J9 189.09,94.89 v1(189.72,94.26) 189.72,94.25 ; U1.J9 188.45,95.52 v1(188.45,95.54) 187.82,96.16 U1.K10 ; U1.J9 U1.H10 v1(188.45,92.98) 189.72,94.25 ; U2.116 90.73,44.14 v2(91.04,43.84) ; LD10.2 54.18,178.59 v2(54.19,178.61) ; U2.33 81.38,27.77 v2(81.37,27.77) ; U1.J2 v1(198.64,94.22) ; v2(109.74,191.6) 110.06,191.28 U13.5 ; U2.93 97.64,39.27 v2(97.64,39.27) ; v1(179.55,87.91) U1.D16 ; U1.D16 v1(180.82,89.18) ; U1.D16 v1(180.82,87.91) ; U1.U1 v1(200.45,105.05) ; v1(196.07,104.42) U1.T3 196.73,103.78 v1(197.35,103.17) ; v1(196.07,104.42) 195.43,103.78 U1.T4 ; U1.T2 197.96,103.78 v1(197.35,103.17) ; U14.46 175.35,45.85 175.94,46.43 C173.2 ; 129.33,188.72 128.72,188.72 128.68,188.68 U16.13 ; 129.33,188.72 U16.14 ; v1(189.69,93) 189.69,93.01 189.08,93.62 U1.H9 188.45,94.25 v1(188.45,94.25) 187.81,94.89 U1.J10 U1.K9 v1(189.7,95.54) U1.J8 190.35,94.89 v1(190.98,94.26) ; C172.2 176.63,38.35 U14.31 ; U2.3 84.3,42.77 v2(84.8,43.27) 85.14,43.27 86.23,44.36 U2.125 ; U1.H3 v1(197.3,93.02) U1.G2 ; v1(198.62,99.35) 197.98,98.7 U1.M2 ; v1(184.69,84.04) 184.69,84.04 184.67,84.06 184.67,84.06 184,84.73 U1.A13 ; v1(199.9,109.56) 199.9,109.52 199.25,108.86 U1.Y1 ; U5.L12 125.22,94.24 v1(125.71,93.75) ; v1(179.54,99.33) 178.92,98.7 U1.M17 ; U1.H12 185.9,92.99 v1(185.91,92.99) 186.54,93.62 U1.H11 185.91,94.25 v1(185.91,94.26) ; U14.7 153.23,43.85 v2(153.07,43.69) ; U1.B8 190.35,86 v1(190.96,86.61) 191.57,86 U1.B7 191.62,86 v1(192.25,85.37) 191.62,84.73 U1.A7 ; v1(194.83,90.49) 195.43,89.89 U1.E4 195.43,89.81 v1(194.8,89.19) 194.8,89.17 ; U2.49 89.73,24.73 v2(90.2,25.19) ; R124.1 170.52,206.11 v2(170.52,206.11) ; U1.B2 197.97,86 199.24,84.74 U1.A1 ; 194.8,89.17 U1.D4 195.43,88.53 v1(194.8,87.9) U1.D5 194.79,89.17 194.8,89.17 ; U5.N26 139.23,92.25 v1(139.72,91.75) ; v1(174.25,90.51) 174.53,90.51 175.11,91.08 U1.F20 ; U2.80 97.42,32.77 v2(97.42,32.77) ; v2(126.42,193.32) 126.43,193.32 U16.10 ; U1.F17 v1(179.55,90.45) U1.E17 v1(178.28,90.45) U1.F17 ; U1.F17 178.93,91.08 v1(179.65,91.81) ; 189.72,94.25 U1.H8 190.35,93.62 v1(190.94,93.03) ; v2(119.16,114.22) 119.16,114.23 R40.3 ; v2(159.06,43.82) 156.54,46.35 U14.2 ; v2(122.76,165.77) 122.76,165.77 C181.2 123.7,164.94 v2(123.72,164.91) 123.72,164.91 U15.3 ; v2(85.08,34.44) 84.9,34.27 U2.20 ; v1(189.72,105.69) 189.09,106.32 U1.V9 ; v2(100.71,24.97) 100.41,25.27 U2.65 ; U1.Y17 178.92,108.87 v1(179.48,109.43) ; U1.W8 190.36,107.59 v1(190.99,106.96) 190.99,106.96 U1.W7 191.62,107.59 v1(192.26,108.23) 191.62,108.86 U1.Y7 ; C215.2 v2(62.84,56.85) ; U1.U13 184.6,104.45 v1(184.6,104.34) ; R97.1 134.69,168.32 v2(134.69,168.33) ; U1.L4 195.43,97.43 v1(196.07,96.8) 195.43,96.16 U1.K4 ; U1.Y20 v1(174.47,109.5) ; C162.2 176.69,41.08 175.92,41.08 175.69,40.85 U14.36 ; U24.5 v2(204.85,123.91) ; U1.G2 v1(198.6,91.72) U1.F2 v1(197.33,91.72) U1.G2 ; C263.2 v1(81.66,85.8) ; v1(174.47,84.1) U1.A20 ; U2.27 v2(84.77,30.77) ; U1.V18 177.65,106.32 v1(178.27,105.7) 178.92,105.06 U1.U17 178.93,105.05 v1(179.52,104.46) ; C265.2 v1(64.11,77.72) ; U1.N3 v1(197.31,100.58) U1.P2 ; U1.C9 189.08,87.28 v1(189.69,87.89) ; C262.2 v1(79.22,91.75) ; U1.D13 v1(183.34,89.2) ; U1.W2 v1(197.39,108.17) ; 185.91,99.34 U1.N12 v1(184.63,100.61) 184.63,100.59 v1(183.37,99.34) 184,98.71 U1.M13 v1(184.64,98.06) U1.L12 U1.M11 186.54,98.71 v1(185.91,99.34) 185.91,99.34
  TOP w0.381: C1_LF.2 v1(198.96,159.41) R2_LF.1
  TOP w0.508: v2(163.98,177.41) C248.2 v2(163.12,176.44) ; v2(65.14,62.32) 65.15,62.32 U19.9 65.15,58.67 v2(65.14,58.66) ; C138.1 v1(198.65,166.93) ; C206.2 124.44,194.96 v2(124.44,194.96) ; v2(82.89,171.98) 82.9,171.98 D1.1 ; R92.1 v1(95.06,162.32) ; C246.2 204.2,176.77 v2(204.19,176.76) ; Y2.2 126.38,62.82 v2(126.39,62.81) ; Y2.2 v2(124.74,61.21) ; Y2.2 v2(124.74,64.49) ; Y2.2 123.06,62.82 v2(123.04,62.84) ; v2(63.75,47.12) 63.75,47.11 C216.2 ; v2(78.7,30.17) 78.7,30.17 C63.2 77.51,31.27 v2(77.5,31.28) ; v2(158.82,203.4) C228.2 157.61,202.28 v2(157.61,202.28) ; v4(86.59,9.53) 86.59,8.36 86.69,8.26 U4.4 ; v4(86.59,9.53) v4(86.59,10.36) ; v4(86.59,9.53) U4.3 ; C149.1 v1(186.69,155.7) ; v1(122.08,69.14) C78.2 v1(121.08,70.26) ; C155.1 v1(197.28,150.14) ; R95.1 v1(95.28,172.01) ; R137.2 195.96,179.37 v1(195.95,179.38) ; R108.1 v2(124.4,196.48) ; C136.2 v2(168.01,53.88) ; U3.2 123.02,12.71 v2(123.48,13.17) 123.97,12.68 U3.1 ; v2(78.28,50.78) 78.27,50.78 C64.2 ; v1(193.83,176.91) Y3.2 v1(192.57,175.51) ; v1(197.4,203.66) U18.9 v1(197.4,200.34) ; C223.2 178.39,198.47 v2(178.39,198.47) ; v2(137.58,192.03) 137.57,192.02 136.45,192.02 C190.2 136.45,191.13 v2(136.46,191.12) ; v2(76.17,180.57) 76.17,180.57 C157.2 ; v2(81.26,146.17) 81.27,146.18 C197.2 82.11,147.35 v2(82.11,147.35) 82.11,147.36 C239.2 ; v4(86.59,10.36) 86.59,10.69 86.69,10.79 U4.2 ; v4(86.59,10.36) R20.3 ; C239.2 83.36,149.11 v2(83.36,149.11) ; C239.2 82.11,150.45 v2(82.11,150.46) ; v2(210.93,122.94) C245.2 v2(209.89,121.9) ; v2(185.81,206.11) 185.8,206.1 R117.1 ; U19.3 v2(60.75,59.84) 59.81,59.84 C214.2 v2(59.78,60.85) ; v2(127.89,163.82) 127.89,163.82 v1(127.89,164.69) U15.9 v1(127.89,165.56) v1(127.89,166.45) v2(127.89,167.34) ; R126.2 156.15,60.01 v2(156.16,60.01) ; C188.1 134.87,191.13 v2(134.87,191.12) ; v2(125.16,161.79) 125.17,161.78 C182.2 ; C237.2 v2(94.26,153.24) ; v2(82.11,142.82) C243.2 83.29,141.56 v2(83.29,141.56) ; U23.11 87.74,158.92 87.75,158.92 v2(87.75,158.25) 88.4,158.9 88.4,159.28 88.39,159.28 U23.12 ; v2(104.98,190.9) 104.97,190.9 R89.1 ; v2(74.7,183.06) 74.71,183.07 C157.2 ; v2(160.6,202.39) 160.61,202.38 C229.2 161.42,201.44 v2(161.44,201.41) U22.3 ; v2(124.38,198.07) 124.39,198.06 R107.1 ; C174.2 177.51,43.74 v2(177.52,43.74) ; C267.2 v2(84.06,190.89) ; 144.5,43.31 144.5,44.29 v2(144.5,44.3) ; C157.2 76.17,185.59 v2(76.17,185.59) ; C157.2 77.48,183.07 v2(77.49,183.06) ; U18.3 v2(193.21,201.38) 193.18,201.4 C208.2 v2(192.35,202.26) ; v2(56.76,60.72) C213.2 58.08,61.84 v2(58.09,61.84) ; C240.2 v1(201.57,166.88) ; v2(177.52,46.42) 177.51,46.43 C173.2 ; 110.4,200.88 v2(111.09,200.18) ; 110.4,200.88 v2(111.09,201.57) ; 110.4,200.88 C159.2 109.13,200.88 ; 109.13,200.88 v2(108.43,201.57) ; 109.13,200.88 v2(108.43,200.18) ; v2(81.26,138.22) 81.27,138.23 C184.2 82.22,139.42 v2(82.23,139.41) ; v2(80.21,187.61) 80.21,187.62 U21.2 ; U8.8 v2(160.94,59.78) ; C64.2 v2(79.97,52.32) ; C64.2 v2(78.27,53.95) ; C162.2 v2(177.49,41.08) ; v2(107.7,191.6) 107.7,191.6 v2(109.74,191.6) 111.82,191.6 v2(111.83,191.6) ; v2(194.83,198.45) 194.83,198.46 C209.2 ; C77.2 v2(166.45,53.99) ; U29.2 v2(82.77,193.19) ; C145.1 v1(196.57,163.19) ; v2(92.79,174.25) 92.79,174.24 C236.2 ; v2(127.6,190.34) 127.61,190.35 U16.21 133.15,190.35 v2(133.15,190.34) ; v2(171.54,193.53) C231.2 ; C201.2 v1(162.18,179.25) ; v1(109.2,183.81) 109.72,184.33 C161.2 ; v2(162.84,59.37) 162.84,59.36 v1(162.84,57.96) v1(162.84,57.07) v1(162.84,56.21) 162.84,54.63 v2(162.84,54.62) ; v2(71.5,57.6) 71.51,57.61 R111.1 ; C266.2 v2(83.41,196.68) ; C140.1 v1(192.46,163.09) ; v2(180.88,203.96) U20.9 v2(180.88,200.54) ; R109.1 v1(203.79,199.16) ; C156.1 v1(193.7,149.4) ; C74.2 v2(149.58,60.74) ; C143.2 v1(190.93,163.14) ; T2.3 v1(200.9,128.66) ; v1(202.9,181.91) 202.9,181.91 U25.5 ; C177.2 v2(108.14,183.9) ; 75.82,26.77 v1(74.92,26.77) ; C137.1 v1(200.05,166.93) ; C180.2 120.62,166.88 v2(120.62,166.89) ; C193.2 v2(134.21,195.7) ; v2(177.49,38.42) 177.49,38.41 C172.2 ; v2(165.1,205.48) C234.2 ; v2(125.76,11.66) C67.2 ; C218.2 196.73,205.41 v1(196.73,205.41) ; v2(175.8,202.65) 175.81,202.64 C222.2 176.64,201.59 v2(176.66,201.58) 176.67,201.57 U20.3 ; v2(195.93,193.63) 195.94,193.62 C210.2 ; T2.5 v1(201.56,126.36) ; U4.7 v2(94.39,10.79) ; R197.2 v1(197.89,152.04) ; C153.2 v1(200.48,156.24) ; v2(134.11,198.71) 134.11,198.71 C192.2 135.28,197.5 v2(135.29,197.51) ; v2(113.33,190.9) 113.33,190.89 R90.1 ; C220.2 v2(64.83,64.01) ; v2(127.16,158.36) 127.17,158.36 C183.2 v2(126.17,159.4) ; v2(84.01,20.61) 84,20.61 C57.2 83.05,21.8 v2(83.05,21.8) ; R69.2 v1(191.67,163.83) ; v2(180.32,205.74) 180.31,205.73 C227.2 ; R78.1 v1(197.31,148.79) ; C71.2 v2(72.27,35.38) ; C175.2 v2(106.58,183.98) ; U23.10 87.74,166.16 87.75,166.17 87.75,167 v1(88.07,167.32) 88.4,167 88.4,166.15 88.39,166.15 U23.9 ; T2.1 v1(202.22,128.66) ; R70.2 v1(195.2,165.76) ; C70.2 v2(72.16,46.81) ; D5.1 v2(79.98,171.98) ; v2(91.74,14.4) 91.76,14.39 C68.2 v2(90.73,13.51) ; v2(174.08,203.52) 174.08,203.51 C221.2 172.76,202.43 v2(172.76,202.44) ; C205.2 v2(125.98,185.01) ; R135.2 196.07,181.03 v1(196.05,181.04) ; C176.2 v2(111.44,184.04) ; 202.31,160.32 v1(203.07,160.32) ; R67.2 v1(191.69,169.34) ; v2(189.26,202.25) 189.27,202.24 C207.2 v2(190.61,203.38) ; C144.2 v1(186.66,157.71) ; v2(170.84,53.92) 170.84,53.93 C241.2 v2(169.79,52.98) ; v2(166.05,198.49) 166.05,198.49 C230.2 ; C171.2 153.29,33.05 v2(153.29,33.05) ; v2(94.24,22.11) 94.8,22.11 95.04,21.87 C58.2 ; C235.2 v2(95.16,163.6) ; R68.2 v1(191.69,165.35) ; R196.2 v1(197.97,154.41)
  TOP w0.635: C158.2 v2(87.63,174.18)
  TOP w0.762: 158.45,186.4 v2(158.45,187.78) v2(158.45,189.31) v2(158.45,190.83) v2(158.45,192.36) ; 158.45,186.4 v2(158.42,186.38) ; 158.45,186.4 U17.3 v2(158.45,181.24) ; v2(183.93,189.86) C225.2 v2(185.16,191.22) ; v2(165.35,192.38) 165.33,192.36 v2(163.02,192.36) v2(161.5,192.36) v2(159.97,192.36) v2(158.45,192.36) ; v2(156.73,177.85) 156.75,177.87 C196.2 157.9,178.86 v2(157.9,178.85) ; v2(165.56,200.23) 165.57,200.23 U22.9 165.57,203.89 v2(165.57,203.9) ; v2(158.45,192.36) v2(158.45,193.88) v2(158.45,195.4) v2(158.45,196.93) v2(158.45,197.94) ; v2(158.45,192.36) v2(156.92,192.36) v2(155.4,192.36) v2(153.88,192.36) 151.87,192.36 v2(151.85,192.38) ; v2(119.3,167.18) 119.29,167.17 C170.2 118.28,166.09 v2(118.28,166.08) ; C195.2 144.34,183.24 v2(144.35,183.25) ; v2(84.04,181.09) 84.04,181.08 C160.2 v2(85.31,179.95) ; v2(144.97,176.67) 144.97,176.67 C194.2 ; v2(153,178.02) 153.01,178.02 C198.2 154.48,176.94 v2(154.47,176.94) ; v2(184.17,193.55) C224.2 v2(183.09,194.63) ; v2(147.97,174.95) 147.97,174.95 C194.2 ; v2(172.7,191.53) C232.2 v2(171.46,190.14) ; v2(64.71,46.03) 64.71,46.04 C216.2 ; v2(62.65,49.59) 62.65,49.59 C217.2 63.87,51.03 v2(63.88,51.03) ; v2(93.42,162.86) 93.41,162.86 U23.21 87.92,162.86 v2(87.92,162.86) ; v2(106.06,168.97) 106.05,168.98 C168.2 104.73,170.05 v2(104.71,170.07) ; C194.2 v2(147.97,178.31) ; C194.2 150.84,176.67 v2(150.84,176.67) ; v2(163.41,163.87) C244.2 162.28,162.62 v2(162.28,162.61) ; v2(119.09,170.18) 119.11,170.17 C169.2 120.34,168.98 v2(120.36,169.01) ; v2(194.78,191.25) 194.78,191.25 C211.2 196.11,189.83 v2(196.1,189.83) ; v2(103.86,166.14) 103.87,166.15 C167.2 104.87,167.19 v2(104.88,167.2) ; v2(163.13,167.51) 163.12,167.51 C242.2 164.46,166.16 v2(164.47,166.17)
  GND1 w0.356: 116.79,24.94 J44.8 ; J44.8 119.02,24.94 ; J44.8 117.91,23.82 ; J44.8 117.07,24.1 ; J44.8 118.75,25.78 ; J44.8 117.07,25.78 ; J44.8 118.75,24.1 ; J44.8 117.91,26.06 ; 144.99,131.74 RCOUT1+.4 ; RCOUT1+.4 147.17,130.81 ; RCOUT1+.4 144.99,129.88 ; RCOUT1+.4 145.92,129.56 ; RCOUT1+.4 145.92,132.06 ; RCOUT1+.4 144.68,130.81 ; RCOUT1+.4 146.85,129.88 ; RCOUT1+.4 146.85,131.74 ; MT3.1 55.24,207.18 ; MT3.1 53.17,205.1 ; MT3.1 56.76,203.59 ; MT3.1 53.73,206.62 ; MT3.1 55.24,203.03 ; MT3.1 56.76,206.62 ; MT3.1 57.32,205.1 ; MT3.1 53.73,203.59 ; 53.73,2.93 MT1.1 ; MT1.1 57.32,4.45 ; MT1.1 55.24,6.52 ; MT1.1 56.76,5.96 ; MT1.1 56.76,2.93 ; MT1.1 53.17,4.45 ; MT1.1 53.73,5.96 ; MT1.1 55.24,2.37 ; 133.86,121.94 DCLKQ+.3 ; DCLKQ+.3 132.93,124.12 ; DCLKQ+.3 133.86,124.44 ; DCLKQ+.3 134.79,122.26 ; DCLKQ+.3 134.79,124.12 ; DCLKQ+.3 132.61,123.19 ; DCLKQ+.3 132.93,122.26 ; DCLKQ+.3 135.1,123.19 ; 132.93,129.88 DCLKQ-.4 ; DCLKQ-.4 132.61,130.81 ; DCLKQ-.4 135.1,130.81 ; DCLKQ-.4 132.93,131.74 ; DCLKQ-.4 133.86,132.06 ; DCLKQ-.4 133.86,129.56 ; DCLKQ-.4 134.79,129.88 ; DCLKQ-.4 134.79,131.74 ; 208.97,206.62 MT4.1 ; MT4.1 212.56,205.1 ; MT4.1 208.97,203.59 ; MT4.1 210.49,207.18 ; MT4.1 212,206.62 ; MT4.1 208.42,205.1 ; MT4.1 212,203.59 ; MT4.1 210.49,203.03 ; J4.15 166.25,143.66 ; J4.15 166.96,142.03 ; J4.15 165.54,142.03 ; J4.15 166.96,143.44 ; J4.15 165.32,142.74 ; J4.15 167.18,142.74 ; J4.15 166.25,141.81 ; J4.15 165.54,143.44 ; TP6.1 85.42,129.14 ; TP6.1 84.58,129.41 ; TP6.1 83.46,128.3 ; TP6.1 83.74,127.45 ; TP6.1 84.58,127.18 ; TP6.1 85.42,127.45 ; TP6.1 85.7,128.3 ; TP6.1 83.74,129.14 ; 137.69,123.19 DCLKQ+.2 ; DCLKQ+.2 139.87,122.26 ; DCLKQ+.2 140.18,123.19 ; DCLKQ+.2 138.01,122.26 ; DCLKQ+.2 138.94,124.44 ; DCLKQ+.2 138.94,121.94 ; DCLKQ+.2 139.87,124.12 ; DCLKQ+.2 138.01,124.12 ; J44.4 122.99,26.06 ; J44.4 122.15,25.78 ; J44.4 122.15,24.1 ; J44.4 124.1,24.94 ; J44.4 122.99,23.82 ; J44.4 123.83,24.1 ; J44.4 123.83,25.78 ; J44.4 121.87,24.94 ; J4.24 159.56,142.74 ; J4.24 159.34,143.44 ; J4.24 157.92,143.44 ; J4.24 158.63,143.66 ; J4.24 157.92,142.03 ; J4.24 158.63,141.81 ; J4.24 159.34,142.03 ; J4.24 157.7,142.74 ; 170.62,143.44 J4.9 ; J4.9 172.04,142.03 ; J4.9 172.04,143.44 ; J4.9 170.4,142.74 ; J4.9 171.33,143.66 ; J4.9 171.33,141.81 ; J4.9 172.26,142.74 ; J4.9 170.62,142.03 ; MT5.1 116.66,123 ; MT5.1 116.66,118.86 ; MT5.1 115.15,122.44 ; MT5.1 115.15,119.41 ; MT5.1 114.59,120.93 ; MT5.1 118.18,119.41 ; MT5.1 118.18,122.44 ; MT5.1 118.73,120.93 ; 152.84,143.44 J4.30 ; J4.30 152.84,142.03 ; J4.30 153.55,141.81 ; J4.30 154.26,143.44 ; J4.30 154.26,142.03 ; J4.30 153.55,143.66 ; J4.30 152.62,142.74 ; J4.30 154.48,142.74 ; 127.31,6.13 SW1.2 ; SW1.2 128.57,4.87 ; SW1.2 129.83,6.13 ; SW1.2 129.51,7.07 ; SW1.2 129.51,5.19 ; SW1.2 127.63,7.07 ; SW1.2 127.63,5.19 ; SW1.2 128.57,7.39 ; J4.12 168.79,143.66 ; J4.12 169.5,142.03 ; J4.12 168.08,143.44 ; J4.12 168.08,142.03 ; J4.12 169.5,143.44 ; J4.12 167.86,142.74 ; J4.12 169.72,142.74 ; J4.12 168.79,141.81 ; 113.84,11.22 J25.5 ; J25.5 115.26,12.64 ; J25.5 114.55,11 ; J25.5 115.26,11.22 ; J25.5 113.62,11.93 ; J25.5 115.48,11.93 ; J25.5 114.55,12.86 ; J25.5 113.84,12.64 ; 114.53,25.78 J44.10 ; J44.10 115.37,26.06 ; J44.10 114.53,24.1 ; J44.10 114.25,24.94 ; J44.10 116.48,24.94 ; J44.10 115.37,23.82 ; J44.10 116.21,25.78 ; J44.10 116.21,24.1 ; RCLK-.5 163.36,125.11 ; RCLK-.5 161.19,126.04 ; RCLK-.5 163.68,126.04 ; RCLK-.5 161.5,125.11 ; RCLK-.5 162.43,127.28 ; RCLK-.5 161.5,126.97 ; RCLK-.5 162.43,124.79 ; RCLK-.5 163.36,126.97 ; 143.23,24.1 J18.4 ; J18.4 143.23,25.78 ; J18.4 144.07,23.82 ; J18.4 145.19,24.94 ; J18.4 144.91,25.78 ; J18.4 144.07,26.06 ; J18.4 142.95,24.94 ; J18.4 144.91,24.1 ; DCLKQ-.5 139.87,129.88 ; DCLKQ-.5 138.01,131.74 ; DCLKQ-.5 138.94,129.56 ; DCLKQ-.5 137.69,130.81 ; DCLKQ-.5 139.87,131.74 ; DCLKQ-.5 140.18,130.81 ; DCLKQ-.5 138.01,129.88 ; DCLKQ-.5 138.94,132.06 ; RCOUT1+.2 151.93,136.82 ; RCOUT1+.2 149.76,135.89 ; RCOUT1+.2 150.07,136.82 ; RCOUT1+.2 151,137.14 ; RCOUT1+.2 152.25,135.89 ; RCOUT1+.2 151,134.64 ; RCOUT1+.2 151.93,134.96 ; RCOUT1+.2 150.07,134.96 ; 160.46,142.03 J4.21 ; J4.21 161.88,142.03 ; J4.21 160.24,142.74 ; J4.21 161.17,141.81 ; J4.21 161.17,143.66 ; J4.21 162.1,142.74 ; J4.21 161.88,143.44 ; J4.21 160.46,143.44 ; RCOUT1-.4 147.17,118.11 ; RCOUT1-.4 146.85,117.18 ; RCOUT1-.4 145.92,116.86 ; RCOUT1-.4 145.92,119.36 ; RCOUT1-.4 144.68,118.11 ; RCOUT1-.4 144.99,119.04 ; RCOUT1-.4 144.99,117.18 ; RCOUT1-.4 146.85,119.04 ; RCLK+.4 170.98,125.11 ; RCLK+.4 170.05,127.28 ; RCLK+.4 168.81,126.04 ; RCLK+.4 169.12,125.11 ; RCLK+.4 169.12,126.97 ; RCLK+.4 170.05,124.79 ; RCLK+.4 171.3,126.04 ; RCLK+.4 170.98,126.97 ; TP9.1 131.91,143.66 ; TP9.1 131.06,145.62 ; TP9.1 131.06,143.38 ; TP9.1 131.91,145.34 ; TP9.1 130.22,145.34 ; TP9.1 129.95,144.5 ; TP9.1 132.18,144.5 ; TP9.1 130.22,143.66 ; 142.07,157.62 TP5.1 ; TP5.1 141.23,157.9 ; TP5.1 140.95,158.74 ; TP5.1 142.91,157.9 ; TP5.1 141.23,159.58 ; TP5.1 143.19,158.74 ; TP5.1 142.07,159.86 ; TP5.1 142.91,159.58 ; 132.61,135.89 DCLKQ-.3 ; DCLKQ-.3 134.79,136.82 ; DCLKQ-.3 133.86,137.14 ; DCLKQ-.3 133.86,134.64 ; DCLKQ-.3 132.93,134.96 ; DCLKQ-.3 134.79,134.96 ; DCLKQ-.3 132.93,136.82 ; DCLKQ-.3 135.1,135.89 ; J4.6 174.8,142.74 ; J4.6 173.87,141.81 ; J4.6 174.58,143.44 ; J4.6 172.94,142.74 ; J4.6 173.16,143.44 ; J4.6 173.87,143.66 ; J4.6 174.58,142.03 ; J4.6 173.16,142.03 ; 175.13,129.87 RCLK+.2 ; RCLK+.2 176.38,131.12 ; RCLK+.2 173.89,131.12 ; RCLK+.2 174.2,132.05 ; RCLK+.2 176.06,130.19 ; RCLK+.2 174.2,130.19 ; RCLK+.2 175.13,132.36 ; RCLK+.2 176.06,132.05 ; 152.23,155.08 J15.1 ; J15.1 153.35,155.08 ; J15.1 153.35,156.2 ; J15.1 151.11,156.2 ; J15.1 151.11,157.32 ; J15.1 153.35,157.32 ; J15.1 151.11,155.08 ; J15.1 152.23,157.32 ; J44.2 125.53,26.06 ; J44.2 124.41,24.94 ; J44.2 124.69,25.78 ; J44.2 125.53,23.82 ; J44.2 124.69,24.1 ; J44.2 126.37,24.1 ; J44.2 126.37,25.78 ; J44.2 126.64,24.94 ; 163,142.03 J4.18 ; J4.18 163.71,143.66 ; J4.18 163,143.44 ; J4.18 164.64,142.74 ; J4.18 164.42,142.03 ; J4.18 162.78,142.74 ; J4.18 164.42,143.44 ; J4.18 163.71,141.81 ; 145.77,25.78 J18.2 ; J18.2 146.61,23.82 ; J18.2 147.45,25.78 ; J18.2 147.45,24.1 ; J18.2 147.73,24.94 ; J18.2 146.61,26.06 ; J18.2 145.77,24.1 ; J18.2 145.49,24.94 ; 136.04,54.91 J6.6 ; J6.6 137.72,54.91 ; J6.6 135.76,55.75 ; J6.6 136.88,54.63 ; J6.6 138,55.75 ; J6.6 137.72,56.59 ; J6.6 136.04,56.59 ; J6.6 136.88,56.87 ; RCLK-.4 158.28,125.11 ; RCLK-.4 158.6,126.04 ; RCLK-.4 157.35,127.28 ; RCLK-.4 156.11,126.04 ; RCLK-.4 158.28,126.97 ; RCLK-.4 156.42,125.11 ; RCLK-.4 156.42,126.97 ; RCLK-.4 157.35,124.79 ; DCLKQ-.2 138.94,137.14 ; DCLKQ-.2 139.87,134.96 ; DCLKQ-.2 139.87,136.82 ; DCLKQ-.2 138.94,134.64 ; DCLKQ-.2 137.69,135.89 ; DCLKQ-.2 140.18,135.89 ; DCLKQ-.2 138.01,134.96 ; DCLKQ-.2 138.01,136.82 ; 138.99,23.82 J18.8 ; J18.8 138.15,24.1 ; J18.8 139.83,24.1 ; J18.8 137.87,24.94 ; J18.8 140.11,24.94 ; J18.8 139.83,25.78 ; J18.8 138.99,26.06 ; J18.8 138.15,25.78 ; 152.23,166.65 J17.1 ; J17.1 153.35,168.88 ; J17.1 153.35,166.65 ; J17.1 152.23,168.88 ; J17.1 151.11,168.88 ; J17.1 151.11,166.65 ; J17.1 151.11,167.76 ; J17.1 153.35,167.76 ; 162.43,129.87 RCLK-.2 ; RCLK-.2 163.68,131.12 ; RCLK-.2 161.5,130.19 ; RCLK-.2 163.36,132.05 ; RCLK-.2 163.36,130.19 ; RCLK-.2 161.19,131.12 ; RCLK-.2 161.5,132.05 ; RCLK-.2 162.43,132.36 ; 158.45,48.31 TP8.1 ; TP8.1 157.33,49.43 ; TP8.1 159.29,50.27 ; TP8.1 159.29,48.59 ; TP8.1 157.6,48.59 ; TP8.1 158.45,50.55 ; TP8.1 159.56,49.43 ; TP8.1 157.6,50.27 ; J4.3 176.41,143.66 ; J4.3 175.7,143.44 ; J4.3 176.41,141.81 ; J4.3 177.34,142.74 ; J4.3 177.12,143.44 ; J4.3 175.7,142.03 ; J4.3 175.48,142.74 ; J4.3 177.12,142.03 ; 82.09,66.22 TP7.1 ; TP7.1 81.25,68.18 ; TP7.1 80.97,67.34 ; TP7.1 82.93,68.18 ; TP7.1 82.09,68.45 ; TP7.1 81.25,66.49 ; TP7.1 82.93,66.49 ; TP7.1 83.21,67.34 ; 132.61,118.11 DCLKQ+.4 ; DCLKQ+.4 135.1,118.11 ; DCLKQ+.4 132.93,119.04 ; DCLKQ+.4 134.79,119.04 ; DCLKQ+.4 134.79,117.18 ; DCLKQ+.4 132.93,117.18 ; DCLKQ+.4 133.86,119.36 ; DCLKQ+.4 133.86,116.86 ; 149.76,130.81 RCOUT1+.5 ; RCOUT1+.5 151,129.56 ; RCOUT1+.5 150.07,129.88 ; RCOUT1+.5 152.25,130.81 ; RCOUT1+.5 151,132.06 ; RCOUT1+.5 151.93,131.74 ; RCOUT1+.5 150.07,131.74 ; RCOUT1+.5 151.93,129.88 ; RCLK+.5 176.06,126.97 ; RCLK+.5 174.2,126.97 ; RCLK+.5 174.2,125.11 ; RCLK+.5 176.38,126.04 ; RCLK+.5 175.13,127.28 ; RCLK+.5 176.06,125.11 ; RCLK+.5 173.89,126.04 ; RCLK+.5 175.13,124.79 ; 156.09,141.81 J4.27 ; J4.27 155.38,143.44 ; J4.27 155.16,142.74 ; J4.27 156.8,142.03 ; J4.27 155.38,142.03 ; J4.27 156.09,143.66 ; J4.27 157.02,142.74 ; J4.27 156.8,143.44 ; RCOUT1+.3 146.85,134.96 ; RCOUT1+.3 147.17,135.89 ; RCOUT1+.3 144.99,134.96 ; RCOUT1+.3 144.99,136.82 ; RCOUT1+.3 144.68,135.89 ; RCOUT1+.3 145.92,137.14 ; RCOUT1+.3 146.85,136.82 ; RCOUT1+.3 145.92,134.64 ; 119.35,36.19 TP11.1 ; TP11.1 120.2,38.15 ; TP11.1 120.2,36.47 ; TP11.1 120.47,37.31 ; TP11.1 118.51,38.15 ; TP11.1 118.51,36.47 ; TP11.1 119.35,38.43 ; TP11.1 118.24,37.31 ; 140.69,25.78 J18.6 ; J18.6 142.37,24.1 ; J18.6 142.37,25.78 ; J18.6 142.65,24.94 ; J18.6 141.53,23.82 ; J18.6 140.41,24.94 ; J18.6 141.53,26.06 ; J18.6 140.69,24.1 ; 145.92,121.94 RCOUT1-.3 ; RCOUT1-.3 146.85,122.26 ; RCOUT1-.3 147.17,123.19 ; RCOUT1-.3 146.85,124.12 ; RCOUT1-.3 145.92,124.44 ; RCOUT1-.3 144.68,123.19 ; RCOUT1-.3 144.99,124.12 ; RCOUT1-.3 144.99,122.26 ; 137.69,118.11 DCLKQ+.5 ; DCLKQ+.5 138.94,116.86 ; DCLKQ+.5 138.01,117.18 ; DCLKQ+.5 138.94,119.36 ; DCLKQ+.5 138.01,119.04 ; DCLKQ+.5 139.87,117.18 ; DCLKQ+.5 139.87,119.04 ; DCLKQ+.5 140.18,118.11 ; 111.3,11.22 J25.6 ; J25.6 112.01,11 ; J25.6 112.94,11.93 ; J25.6 112.72,11.22 ; J25.6 112.72,12.64 ; J25.6 111.08,11.93 ; J25.6 112.01,12.86 ; J25.6 111.3,12.64 ; TP10.1 174.35,162.94 ; TP10.1 174.63,163.78 ; TP10.1 174.35,164.62 ; TP10.1 172.67,164.62 ; TP10.1 172.39,163.78 ; TP10.1 173.51,162.66 ; TP10.1 172.67,162.94 ; TP10.1 173.51,164.9 ; J2.4 70.39,12.44 ; J2.4 69.08,12.19 ; J2.4 70.64,13.75 ; J2.4 68.43,13.28 ; J2.4 68.46,12.81 ; J2.4 68.71,12.44 ; J2.4 69.55,12.17 ; J2.4 70.67,13.28 ; RCLK+.3 170.98,130.19 ; RCLK+.3 170.05,129.87 ; RCLK+.3 169.12,132.05 ; RCLK+.3 168.81,131.12 ; RCLK+.3 171.3,131.12 ; RCLK+.3 169.12,130.19 ; RCLK+.3 170.05,132.36 ; RCLK+.3 170.98,132.05 ; L9.3 67.28,170.2 ; L9.3 66.26,169.85 ; L9.3 65.24,170.2 ; L9.3 64.89,171.22 ; L9.3 65.24,172.24 ; L9.3 67.28,172.24 ; L9.3 65.69,169.89 ; L9.3 66.26,172.59 ; 156.11,131.12 RCLK-.3 ; RCLK-.3 157.35,132.36 ; RCLK-.3 158.6,131.12 ; RCLK-.3 156.42,132.05 ; RCLK-.3 157.35,129.87 ; RCLK-.3 158.28,132.05 ; RCLK-.3 156.42,130.19 ; RCLK-.3 158.28,130.19 ; MT2.1 210.49,6.52 ; MT2.1 208.97,5.96 ; MT2.1 212,2.93 ; MT2.1 212.56,4.45 ; MT2.1 208.42,4.45 ; MT2.1 212,5.96 ; MT2.1 210.49,2.37 ; MT2.1 208.97,2.93 ; 136.45,23.82 J18.10 ; J18.10 136.45,26.06 ; J18.10 135.61,25.78 ; J18.10 135.61,24.1 ; J18.10 135.33,24.94 ; J18.10 137.29,24.1 ; J18.10 137.29,25.78 ; J18.10 137.57,24.94 ; 119.61,24.1 J44.6 ; J44.6 121.29,25.78 ; J44.6 119.61,25.78 ; J44.6 121.56,24.94 ; J44.6 121.29,24.1 ; J44.6 120.45,23.82 ; J44.6 119.33,24.94 ; J44.6 120.45,26.06 ; 149.76,118.11 RCOUT1-.5 ; RCOUT1-.5 150.07,119.04 ; RCOUT1-.5 151.93,119.04 ; RCOUT1-.5 150.07,117.18 ; RCOUT1-.5 151,119.36 ; RCOUT1-.5 151,116.86 ; RCOUT1-.5 151.93,117.18 ; RCOUT1-.5 152.25,118.11 ; RCOUT1-.2 151,124.44 ; RCOUT1-.2 151.93,122.26 ; RCOUT1-.2 151,121.94 ; RCOUT1-.2 151.93,124.12 ; RCOUT1-.2 150.07,124.12 ; RCOUT1-.2 150.07,122.26 ; RCOUT1-.2 152.25,123.19 ; RCOUT1-.2 149.76,123.19
  PWR1 w0.305: 120.42,89.33 121.12,89.33 v1(121.71,88.75)
  GND2 w0.356: 150.07,117.18 RCOUT1-.5 ; RCOUT1-.5 151,116.86 ; RCOUT1-.5 149.76,118.11 ; RCOUT1-.5 151.93,119.04 ; RCOUT1-.5 151.93,117.18 ; RCOUT1-.5 150.07,119.04 ; RCOUT1-.5 151,119.36 ; RCOUT1-.5 152.25,118.11 ; 135.76,55.75 J6.6 ; J6.6 138,55.75 ; J6.6 137.72,54.91 ; J6.6 136.04,56.59 ; J6.6 136.04,54.91 ; J6.6 136.88,56.87 ; J6.6 137.72,56.59 ; J6.6 136.88,54.63 ; 145.92,116.86 RCOUT1-.4 ; RCOUT1-.4 147.17,118.11 ; RCOUT1-.4 144.99,119.04 ; RCOUT1-.4 145.92,119.36 ; RCOUT1-.4 144.68,118.11 ; RCOUT1-.4 146.85,117.18 ; RCOUT1-.4 144.99,117.18 ; RCOUT1-.4 146.85,119.04 ; TP6.1 85.7,128.3 ; TP6.1 85.42,127.45 ; TP6.1 84.58,127.18 ; TP6.1 84.58,129.41 ; TP6.1 85.42,129.14 ; TP6.1 83.74,127.45 ; TP6.1 83.46,128.3 ; TP6.1 83.74,129.14 ; 161.19,131.12 RCLK-.2 ; RCLK-.2 161.5,130.19 ; RCLK-.2 162.43,132.36 ; RCLK-.2 163.36,132.05 ; RCLK-.2 162.43,129.87 ; RCLK-.2 163.36,130.19 ; RCLK-.2 163.68,131.12 ; RCLK-.2 161.5,132.05 ; 161.5,126.97 RCLK-.5 ; RCLK-.5 162.43,124.79 ; RCLK-.5 161.5,125.11 ; RCLK-.5 162.43,127.28 ; RCLK-.5 163.36,126.97 ; RCLK-.5 163.68,126.04 ; RCLK-.5 161.19,126.04 ; RCLK-.5 163.36,125.11 ; 151,134.64 RCOUT1+.2 ; RCOUT1+.2 150.07,134.96 ; RCOUT1+.2 152.25,135.89 ; RCOUT1+.2 150.07,136.82 ; RCOUT1+.2 151,137.14 ; RCOUT1+.2 149.76,135.89 ; RCOUT1+.2 151.93,134.96 ; RCOUT1+.2 151.93,136.82 ; 157.33,49.43 TP8.1 ; TP8.1 157.6,50.27 ; TP8.1 158.45,50.55 ; TP8.1 157.6,48.59 ; TP8.1 159.56,49.43 ; TP8.1 159.29,50.27 ; TP8.1 159.29,48.59 ; TP8.1 158.45,48.31 ; 208.42,4.45 MT2.1 ; MT2.1 208.97,5.96 ; MT2.1 212,5.96 ; MT2.1 212.56,4.45 ; MT2.1 210.49,6.52 ; MT2.1 210.49,2.37 ; MT2.1 208.97,2.93 ; MT2.1 212,2.93 ; 55.24,2.37 MT1.1 ; MT1.1 55.24,6.52 ; MT1.1 53.73,5.96 ; MT1.1 57.32,4.45 ; MT1.1 56.76,5.96 ; MT1.1 56.76,2.93 ; MT1.1 53.73,2.93 ; MT1.1 53.17,4.45 ; J4.6 174.58,143.44 ; J4.6 173.16,143.44 ; J4.6 173.87,143.66 ; J4.6 172.94,142.74 ; J4.6 174.8,142.74 ; J4.6 174.58,142.03 ; J4.6 173.16,142.03 ; J4.6 173.87,141.81 ; 116.66,118.86 MT5.1 ; MT5.1 118.73,120.93 ; MT5.1 114.59,120.93 ; MT5.1 118.18,119.41 ; MT5.1 115.15,122.44 ; MT5.1 116.66,123 ; MT5.1 115.15,119.41 ; MT5.1 118.18,122.44 ; 175.7,143.44 J4.3 ; J4.3 176.41,143.66 ; J4.3 177.12,142.03 ; J4.3 176.41,141.81 ; J4.3 175.48,142.74 ; J4.3 177.12,143.44 ; J4.3 175.7,142.03 ; J4.3 177.34,142.74 ; 138.94,134.64 DCLKQ-.2 ; DCLKQ-.2 138.01,134.96 ; DCLKQ-.2 138.94,137.14 ; DCLKQ-.2 137.69,135.89 ; DCLKQ-.2 139.87,134.96 ; DCLKQ-.2 140.18,135.89 ; DCLKQ-.2 139.87,136.82 ; DCLKQ-.2 138.01,136.82 ; 138.01,129.88 DCLKQ-.5 ; DCLKQ-.5 138.01,131.74 ; DCLKQ-.5 139.87,129.88 ; DCLKQ-.5 140.18,130.81 ; DCLKQ-.5 138.94,132.06 ; DCLKQ-.5 139.87,131.74 ; DCLKQ-.5 138.94,129.56 ; DCLKQ-.5 137.69,130.81 ; J18.10 137.57,24.94 ; J18.10 136.45,26.06 ; J18.10 135.61,24.1 ; J18.10 137.29,24.1 ; J18.10 137.29,25.78 ; J18.10 135.33,24.94 ; J18.10 135.61,25.78 ; J18.10 136.45,23.82 ; MT4.1 212.56,205.1 ; MT4.1 210.49,207.18 ; MT4.1 212,206.62 ; MT4.1 210.49,203.03 ; MT4.1 208.42,205.1 ; MT4.1 212,203.59 ; MT4.1 208.97,206.62 ; MT4.1 208.97,203.59 ; 138.15,24.1 J18.8 ; J18.8 139.83,25.78 ; J18.8 138.15,25.78 ; J18.8 138.99,26.06 ; J18.8 137.87,24.94 ; J18.8 138.99,23.82 ; J18.8 140.11,24.94 ; J18.8 139.83,24.1 ; 118.51,38.15 TP11.1 ; TP11.1 120.2,38.15 ; TP11.1 120.2,36.47 ; TP11.1 119.35,38.43 ; TP11.1 120.47,37.31 ; TP11.1 119.35,36.19 ; TP11.1 118.51,36.47 ; TP11.1 118.24,37.31 ; 168.81,126.04 RCLK+.4 ; RCLK+.4 170.98,125.11 ; RCLK+.4 171.3,126.04 ; RCLK+.4 170.05,127.28 ; RCLK+.4 169.12,126.97 ; RCLK+.4 169.12,125.11 ; RCLK+.4 170.05,124.79 ; RCLK+.4 170.98,126.97 ; RCLK-.3 158.6,131.12 ; RCLK-.3 158.28,132.05 ; RCLK-.3 157.35,132.36 ; RCLK-.3 156.11,131.12 ; RCLK-.3 156.42,132.05 ; RCLK-.3 158.28,130.19 ; RCLK-.3 157.35,129.87 ; RCLK-.3 156.42,130.19 ; J25.5 115.48,11.93 ; J25.5 114.55,12.86 ; J25.5 113.84,12.64 ; J25.5 113.84,11.22 ; J25.5 115.26,11.22 ; J25.5 114.55,11 ; J25.5 115.26,12.64 ; J25.5 113.62,11.93 ; 170.62,143.44 J4.9 ; J4.9 172.26,142.74 ; J4.9 170.62,142.03 ; J4.9 171.33,141.81 ; J4.9 172.04,143.44 ; J4.9 172.04,142.03 ; J4.9 170.4,142.74 ; J4.9 171.33,143.66 ; 151.11,156.2 J15.1 ; J15.1 151.11,157.32 ; J15.1 151.11,155.08 ; J15.1 153.35,156.2 ; J15.1 153.35,155.08 ; J15.1 152.23,157.32 ; J15.1 152.23,155.08 ; J15.1 153.35,157.32 ; J4.21 162.1,142.74 ; J4.21 161.88,142.03 ; J4.21 160.46,143.44 ; J4.21 161.88,143.44 ; J4.21 161.17,143.66 ; J4.21 160.46,142.03 ; J4.21 160.24,142.74 ; J4.21 161.17,141.81 ; TP10.1 174.63,163.78 ; TP10.1 173.51,162.66 ; TP10.1 172.39,163.78 ; TP10.1 172.67,164.62 ; TP10.1 172.67,162.94 ; TP10.1 174.35,162.94 ; TP10.1 173.51,164.9 ; TP10.1 174.35,164.62 ; 168.81,131.12 RCLK+.3 ; RCLK+.3 170.05,132.36 ; RCLK+.3 169.12,132.05 ; RCLK+.3 170.05,129.87 ; RCLK+.3 169.12,130.19 ; RCLK+.3 170.98,132.05 ; RCLK+.3 171.3,131.12 ; RCLK+.3 170.98,130.19 ; DCLKQ+.5 139.87,117.18 ; DCLKQ+.5 137.69,118.11 ; DCLKQ+.5 139.87,119.04 ; DCLKQ+.5 138.94,116.86 ; DCLKQ+.5 138.01,119.04 ; DCLKQ+.5 140.18,118.11 ; DCLKQ+.5 138.94,119.36 ; DCLKQ+.5 138.01,117.18 ; 122.15,24.1 J44.4 ; J44.4 123.83,24.1 ; J44.4 124.1,24.94 ; J44.4 122.15,25.78 ; J44.4 121.87,24.94 ; J44.4 122.99,23.82 ; J44.4 122.99,26.06 ; J44.4 123.83,25.78 ; J44.8 118.75,25.78 ; J44.8 117.07,24.1 ; J44.8 117.91,26.06 ; J44.8 118.75,24.1 ; J44.8 117.91,23.82 ; J44.8 116.79,24.94 ; J44.8 117.07,25.78 ; J44.8 119.02,24.94 ; J44.10 116.21,24.1 ; J44.10 116.48,24.94 ; J44.10 114.25,24.94 ; J44.10 115.37,23.82 ; J44.10 116.21,25.78 ; J44.10 114.53,24.1 ; J44.10 114.53,25.78 ; J44.10 115.37,26.06 ; 168.08,143.44 J4.12 ; J4.12 169.5,143.44 ; J4.12 168.08,142.03 ; J4.12 168.79,141.81 ; J4.12 167.86,142.74 ; J4.12 168.79,143.66 ; J4.12 169.72,142.74 ; J4.12 169.5,142.03 ; RCLK+.5 176.38,126.04 ; RCLK+.5 175.13,124.79 ; RCLK+.5 176.06,125.11 ; RCLK+.5 176.06,126.97 ; RCLK+.5 174.2,125.11 ; RCLK+.5 173.89,126.04 ; RCLK+.5 174.2,126.97 ; RCLK+.5 175.13,127.28 ; DCLKQ-.3 134.79,136.82 ; DCLKQ-.3 133.86,137.14 ; DCLKQ-.3 132.93,134.96 ; DCLKQ-.3 133.86,134.64 ; DCLKQ-.3 132.93,136.82 ; DCLKQ-.3 134.79,134.96 ; DCLKQ-.3 132.61,135.89 ; DCLKQ-.3 135.1,135.89 ; J4.18 164.42,143.44 ; J4.18 163.71,141.81 ; J4.18 163,142.03 ; J4.18 163.71,143.66 ; J4.18 162.78,142.74 ; J4.18 164.42,142.03 ; J4.18 163,143.44 ; J4.18 164.64,142.74 ; RCOUT1+.5 151,132.06 ; RCOUT1+.5 151.93,129.88 ; RCOUT1+.5 149.76,130.81 ; RCOUT1+.5 150.07,129.88 ; RCOUT1+.5 150.07,131.74 ; RCOUT1+.5 152.25,130.81 ; RCOUT1+.5 151,129.56 ; RCOUT1+.5 151.93,131.74 ; RCLK-.4 158.6,126.04 ; RCLK-.4 158.28,125.11 ; RCLK-.4 156.42,126.97 ; RCLK-.4 156.42,125.11 ; RCLK-.4 156.11,126.04 ; RCLK-.4 157.35,127.28 ; RCLK-.4 157.35,124.79 ; RCLK-.4 158.28,126.97 ; J44.6 121.56,24.94 ; J44.6 121.29,24.1 ; J44.6 121.29,25.78 ; J44.6 120.45,23.82 ; J44.6 119.61,25.78 ; J44.6 119.61,24.1 ; J44.6 119.33,24.94 ; J44.6 120.45,26.06 ; TP9.1 131.91,143.66 ; TP9.1 130.22,143.66 ; TP9.1 131.91,145.34 ; TP9.1 130.22,145.34 ; TP9.1 132.18,144.5 ; TP9.1 131.06,145.62 ; TP9.1 129.95,144.5 ; TP9.1 131.06,143.38 ; J18.4 144.91,25.78 ; J18.4 145.19,24.94 ; J18.4 143.23,25.78 ; J18.4 144.07,26.06 ; J18.4 142.95,24.94 ; J18.4 144.07,23.82 ; J18.4 144.91,24.1 ; J18.4 143.23,24.1 ; RCOUT1-.2 152.25,123.19 ; RCOUT1-.2 151,121.94 ; RCOUT1-.2 151,124.44 ; RCOUT1-.2 151.93,122.26 ; RCOUT1-.2 149.76,123.19 ; RCOUT1-.2 151.93,124.12 ; RCOUT1-.2 150.07,124.12 ; RCOUT1-.2 150.07,122.26 ; RCOUT1+.3 146.85,136.82 ; RCOUT1+.3 144.99,136.82 ; RCOUT1+.3 145.92,137.14 ; RCOUT1+.3 145.92,134.64 ; RCOUT1+.3 147.17,135.89 ; RCOUT1+.3 144.68,135.89 ; RCOUT1+.3 144.99,134.96 ; RCOUT1+.3 146.85,134.96 ; 124.69,24.1 J44.2 ; J44.2 125.53,26.06 ; J44.2 126.37,25.78 ; J44.2 124.69,25.78 ; J44.2 125.53,23.82 ; J44.2 126.37,24.1 ; J44.2 124.41,24.94 ; J44.2 126.64,24.94 ; 152.84,143.44 J4.30 ; J4.30 153.55,141.81 ; J4.30 154.26,143.44 ; J4.30 153.55,143.66 ; J4.30 154.48,142.74 ; J4.30 152.62,142.74 ; J4.30 152.84,142.03 ; J4.30 154.26,142.03 ; TP5.1 142.91,159.58 ; TP5.1 141.23,157.9 ; TP5.1 142.07,159.86 ; TP5.1 142.07,157.62 ; TP5.1 143.19,158.74 ; TP5.1 141.23,159.58 ; TP5.1 140.95,158.74 ; TP5.1 142.91,157.9 ; J18.2 146.61,26.06 ; J18.2 147.73,24.94 ; J18.2 145.77,24.1 ; J18.2 147.45,25.78 ; J18.2 147.45,24.1 ; J18.2 146.61,23.82 ; J18.2 145.77,25.78 ; J18.2 145.49,24.94 ; RCOUT1+.4 146.85,129.88 ; RCOUT1+.4 145.92,132.06 ; RCOUT1+.4 144.99,129.88 ; RCOUT1+.4 146.85,131.74 ; RCOUT1+.4 144.68,130.81 ; RCOUT1+.4 145.92,129.56 ; RCOUT1+.4 147.17,130.81 ; RCOUT1+.4 144.99,131.74 ; 69.08,12.19 J2.4 ; J2.4 70.39,12.44 ; J2.4 69.55,12.17 ; J2.4 68.71,12.44 ; J2.4 68.46,12.81 ; J2.4 68.43,13.28 ; J2.4 70.67,13.28 ; J2.4 70.64,13.75 ; 156.09,141.81 J4.27 ; J4.27 155.38,143.44 ; J4.27 155.38,142.03 ; J4.27 155.16,142.74 ; J4.27 157.02,142.74 ; J4.27 156.8,143.44 ; J4.27 156.09,143.66 ; J4.27 156.8,142.03 ; DCLKQ+.3 135.1,123.19 ; DCLKQ+.3 132.93,124.12 ; DCLKQ+.3 134.79,124.12 ; DCLKQ+.3 133.86,124.44 ; DCLKQ+.3 134.79,122.26 ; DCLKQ+.3 132.61,123.19 ; DCLKQ+.3 133.86,121.94 ; DCLKQ+.3 132.93,122.26 ; SW1.2 129.51,7.07 ; SW1.2 129.83,6.13 ; SW1.2 129.51,5.19 ; SW1.2 128.57,7.39 ; SW1.2 128.57,4.87 ; SW1.2 127.63,5.19 ; SW1.2 127.31,6.13 ; SW1.2 127.63,7.07 ; TP7.1 82.93,68.18 ; TP7.1 81.25,66.49 ; TP7.1 80.97,67.34 ; TP7.1 83.21,67.34 ; TP7.1 82.09,66.22 ; TP7.1 81.25,68.18 ; TP7.1 82.93,66.49 ; TP7.1 82.09,68.45 ; 65.24,172.24 L9.3 ; L9.3 67.28,172.24 ; L9.3 66.26,169.85 ; L9.3 65.69,169.89 ; L9.3 64.89,171.22 ; L9.3 65.24,170.2 ; L9.3 67.28,170.2 ; L9.3 66.26,172.59 ; 157.92,143.44 J4.24 ; J4.24 159.56,142.74 ; J4.24 158.63,143.66 ; J4.24 159.34,142.03 ; J4.24 157.92,142.03 ; J4.24 159.34,143.44 ; J4.24 158.63,141.81 ; J4.24 157.7,142.74 ; 132.61,130.81 DCLKQ-.4 ; DCLKQ-.4 133.86,132.06 ; DCLKQ-.4 132.93,131.74 ; DCLKQ-.4 134.79,129.88 ; DCLKQ-.4 133.86,129.56 ; DCLKQ-.4 135.1,130.81 ; DCLKQ-.4 132.93,129.88 ; DCLKQ-.4 134.79,131.74 ; 138.94,121.94 DCLKQ+.2 ; DCLKQ+.2 139.87,124.12 ; DCLKQ+.2 137.69,123.19 ; DCLKQ+.2 138.01,124.12 ; DCLKQ+.2 138.01,122.26 ; DCLKQ+.2 139.87,122.26 ; DCLKQ+.2 138.94,124.44 ; DCLKQ+.2 140.18,123.19 ; J17.1 153.35,167.76 ; J17.1 153.35,168.88 ; J17.1 153.35,166.65 ; J17.1 152.23,166.65 ; J17.1 151.11,168.88 ; J17.1 152.23,168.88 ; J17.1 151.11,167.76 ; J17.1 151.11,166.65 ; 140.69,25.78 J18.6 ; J18.6 142.37,24.1 ; J18.6 141.53,26.06 ; J18.6 140.69,24.1 ; J18.6 140.41,24.94 ; J18.6 142.65,24.94 ; J18.6 141.53,23.82 ; J18.6 142.37,25.78 ; 144.99,124.12 RCOUT1-.3 ; RCOUT1-.3 145.92,124.44 ; RCOUT1-.3 144.68,123.19 ; RCOUT1-.3 144.99,122.26 ; RCOUT1-.3 146.85,124.12 ; RCOUT1-.3 147.17,123.19 ; RCOUT1-.3 146.85,122.26 ; RCOUT1-.3 145.92,121.94 ; DCLKQ+.4 135.1,118.11 ; DCLKQ+.4 132.93,119.04 ; DCLKQ+.4 133.86,119.36 ; DCLKQ+.4 132.93,117.18 ; DCLKQ+.4 133.86,116.86 ; DCLKQ+.4 134.79,119.04 ; DCLKQ+.4 132.61,118.11 ; DCLKQ+.4 134.79,117.18 ; 173.89,131.12 RCLK+.2 ; RCLK+.2 174.2,130.19 ; RCLK+.2 176.38,131.12 ; RCLK+.2 176.06,130.19 ; RCLK+.2 175.13,129.87 ; RCLK+.2 174.2,132.05 ; RCLK+.2 175.13,132.36 ; RCLK+.2 176.06,132.05 ; 165.54,142.03 J4.15 ; J4.15 166.96,142.03 ; J4.15 165.54,143.44 ; J4.15 166.25,141.81 ; J4.15 166.25,143.66 ; J4.15 165.32,142.74 ; J4.15 166.96,143.44 ; J4.15 167.18,142.74 ; MT3.1 56.76,203.59 ; MT3.1 53.17,205.1 ; MT3.1 53.73,203.59 ; MT3.1 55.24,203.03 ; MT3.1 55.24,207.18 ; MT3.1 53.73,206.62 ; MT3.1 57.32,205.1 ; MT3.1 56.76,206.62 ; J25.6 112.72,12.64 ; J25.6 112.72,11.22 ; J25.6 111.08,11.93 ; J25.6 112.94,11.93 ; J25.6 112.01,12.86 ; J25.6 111.3,12.64 ; J25.6 112.01,11 ; J25.6 111.3,11.22
  GND3 w0.356: 149.76,130.81 RCOUT1+.5 ; RCOUT1+.5 151,132.06 ; RCOUT1+.5 151.93,129.88 ; RCOUT1+.5 150.07,129.88 ; RCOUT1+.5 150.07,131.74 ; RCOUT1+.5 151.93,131.74 ; RCOUT1+.5 151,129.56 ; RCOUT1+.5 152.25,130.81 ; 137.69,135.89 DCLKQ-.2 ; DCLKQ-.2 139.87,134.96 ; DCLKQ-.2 138.01,134.96 ; DCLKQ-.2 138.01,136.82 ; DCLKQ-.2 138.94,137.14 ; DCLKQ-.2 139.87,136.82 ; DCLKQ-.2 140.18,135.89 ; DCLKQ-.2 138.94,134.64 ; 115.15,119.41 MT5.1 ; MT5.1 116.66,118.86 ; MT5.1 116.66,123 ; MT5.1 114.59,120.93 ; MT5.1 118.18,122.44 ; MT5.1 115.15,122.44 ; MT5.1 118.18,119.41 ; MT5.1 118.73,120.93 ; MT2.1 210.49,6.52 ; MT2.1 208.42,4.45 ; MT2.1 210.49,2.37 ; MT2.1 212.56,4.45 ; MT2.1 208.97,5.96 ; MT2.1 212,5.96 ; MT2.1 212,2.93 ; MT2.1 208.97,2.93 ; 132.61,135.89 DCLKQ-.3 ; DCLKQ-.3 135.1,135.89 ; DCLKQ-.3 133.86,137.14 ; DCLKQ-.3 132.93,136.82 ; DCLKQ-.3 132.93,134.96 ; DCLKQ-.3 134.79,136.82 ; DCLKQ-.3 133.86,134.64 ; DCLKQ-.3 134.79,134.96 ; RCOUT1+.3 147.17,135.89 ; RCOUT1+.3 145.92,137.14 ; RCOUT1+.3 144.99,136.82 ; RCOUT1+.3 144.68,135.89 ; RCOUT1+.3 145.92,134.64 ; RCOUT1+.3 144.99,134.96 ; RCOUT1+.3 146.85,136.82 ; RCOUT1+.3 146.85,134.96 ; J44.6 121.56,24.94 ; J44.6 119.33,24.94 ; J44.6 121.29,25.78 ; J44.6 120.45,23.82 ; J44.6 120.45,26.06 ; J44.6 121.29,24.1 ; J44.6 119.61,25.78 ; J44.6 119.61,24.1 ; RCOUT1-.2 151.93,122.26 ; RCOUT1-.2 152.25,123.19 ; RCOUT1-.2 150.07,124.12 ; RCOUT1-.2 149.76,123.19 ; RCOUT1-.2 151.93,124.12 ; RCOUT1-.2 151,124.44 ; RCOUT1-.2 151,121.94 ; RCOUT1-.2 150.07,122.26 ; J18.10 136.45,26.06 ; J18.10 136.45,23.82 ; J18.10 137.57,24.94 ; J18.10 137.29,25.78 ; J18.10 135.61,25.78 ; J18.10 135.33,24.94 ; J18.10 137.29,24.1 ; J18.10 135.61,24.1 ; 132.61,123.19 DCLKQ+.3 ; DCLKQ+.3 133.86,124.44 ; DCLKQ+.3 135.1,123.19 ; DCLKQ+.3 134.79,122.26 ; DCLKQ+.3 134.79,124.12 ; DCLKQ+.3 133.86,121.94 ; DCLKQ+.3 132.93,122.26 ; DCLKQ+.3 132.93,124.12 ; RCLK+.3 170.98,132.05 ; RCLK+.3 169.12,130.19 ; RCLK+.3 170.05,132.36 ; RCLK+.3 168.81,131.12 ; RCLK+.3 170.98,130.19 ; RCLK+.3 170.05,129.87 ; RCLK+.3 171.3,131.12 ; RCLK+.3 169.12,132.05 ; 208.97,203.59 MT4.1 ; MT4.1 212.56,205.1 ; MT4.1 210.49,207.18 ; MT4.1 212,206.62 ; MT4.1 212,203.59 ; MT4.1 208.97,206.62 ; MT4.1 210.49,203.03 ; MT4.1 208.42,205.1 ; TP7.1 82.93,66.49 ; TP7.1 81.25,68.18 ; TP7.1 81.25,66.49 ; TP7.1 80.97,67.34 ; TP7.1 82.09,68.45 ; TP7.1 82.93,68.18 ; TP7.1 83.21,67.34 ; TP7.1 82.09,66.22 ; RCOUT1-.3 146.85,124.12 ; RCOUT1-.3 144.99,124.12 ; RCOUT1-.3 147.17,123.19 ; RCOUT1-.3 144.68,123.19 ; RCOUT1-.3 144.99,122.26 ; RCOUT1-.3 145.92,124.44 ; RCOUT1-.3 145.92,121.94 ; RCOUT1-.3 146.85,122.26 ; RCLK+.4 170.98,125.11 ; RCLK+.4 168.81,126.04 ; RCLK+.4 169.12,126.97 ; RCLK+.4 170.05,124.79 ; RCLK+.4 171.3,126.04 ; RCLK+.4 169.12,125.11 ; RCLK+.4 170.98,126.97 ; RCLK+.4 170.05,127.28 ; 83.46,128.3 TP6.1 ; TP6.1 85.7,128.3 ; TP6.1 84.58,129.41 ; TP6.1 83.74,129.14 ; TP6.1 85.42,129.14 ; TP6.1 85.42,127.45 ; TP6.1 83.74,127.45 ; TP6.1 84.58,127.18 ; 153.55,141.81 J4.30 ; J4.30 153.55,143.66 ; J4.30 152.84,142.03 ; J4.30 154.48,142.74 ; J4.30 154.26,143.44 ; J4.30 152.62,142.74 ; J4.30 154.26,142.03 ; J4.30 152.84,143.44 ; 113.84,12.64 J25.5 ; J25.5 113.84,11.22 ; J25.5 115.48,11.93 ; J25.5 114.55,12.86 ; J25.5 113.62,11.93 ; J25.5 115.26,12.64 ; J25.5 114.55,11 ; J25.5 115.26,11.22 ; DCLKQ+.5 139.87,119.04 ; DCLKQ+.5 138.01,119.04 ; DCLKQ+.5 137.69,118.11 ; DCLKQ+.5 139.87,117.18 ; DCLKQ+.5 140.18,118.11 ; DCLKQ+.5 138.94,119.36 ; DCLKQ+.5 138.01,117.18 ; DCLKQ+.5 138.94,116.86 ; 150.07,134.96 RCOUT1+.2 ; RCOUT1+.2 151.93,136.82 ; RCOUT1+.2 151,134.64 ; RCOUT1+.2 151,137.14 ; RCOUT1+.2 152.25,135.89 ; RCOUT1+.2 150.07,136.82 ; RCOUT1+.2 151.93,134.96 ; RCOUT1+.2 149.76,135.89 ; 132.93,119.04 DCLKQ+.4 ; DCLKQ+.4 133.86,116.86 ; DCLKQ+.4 135.1,118.11 ; DCLKQ+.4 132.61,118.11 ; DCLKQ+.4 133.86,119.36 ; DCLKQ+.4 134.79,117.18 ; DCLKQ+.4 134.79,119.04 ; DCLKQ+.4 132.93,117.18 ; 114.53,25.78 J44.10 ; J44.10 114.53,24.1 ; J44.10 114.25,24.94 ; J44.10 116.21,24.1 ; J44.10 116.21,25.78 ; J44.10 115.37,26.06 ; J44.10 115.37,23.82 ; J44.10 116.48,24.94 ; J6.6 136.88,56.87 ; J6.6 137.72,56.59 ; J6.6 136.88,54.63 ; J6.6 135.76,55.75 ; J6.6 136.04,54.91 ; J6.6 136.04,56.59 ; J6.6 137.72,54.91 ; J6.6 138,55.75 ; J17.1 153.35,168.88 ; J17.1 153.35,167.76 ; J17.1 151.11,166.65 ; J17.1 151.11,168.88 ; J17.1 151.11,167.76 ; J17.1 152.23,166.65 ; J17.1 152.23,168.88 ; J17.1 153.35,166.65 ; 173.89,131.12 RCLK+.2 ; RCLK+.2 175.13,129.87 ; RCLK+.2 176.06,132.05 ; RCLK+.2 176.06,130.19 ; RCLK+.2 175.13,132.36 ; RCLK+.2 176.38,131.12 ; RCLK+.2 174.2,132.05 ; RCLK+.2 174.2,130.19 ; 145.92,129.56 RCOUT1+.4 ; RCOUT1+.4 146.85,131.74 ; RCOUT1+.4 144.99,129.88 ; RCOUT1+.4 145.92,132.06 ; RCOUT1+.4 144.99,131.74 ; RCOUT1+.4 147.17,130.81 ; RCOUT1+.4 146.85,129.88 ; RCOUT1+.4 144.68,130.81 ; 55.24,2.37 MT1.1 ; MT1.1 56.76,2.93 ; MT1.1 57.32,4.45 ; MT1.1 53.73,2.93 ; MT1.1 56.76,5.96 ; MT1.1 53.73,5.96 ; MT1.1 55.24,6.52 ; MT1.1 53.17,4.45 ; 145.77,24.1 J18.2 ; J18.2 147.45,25.78 ; J18.2 146.61,23.82 ; J18.2 147.73,24.94 ; J18.2 146.61,26.06 ; J18.2 145.77,25.78 ; J18.2 147.45,24.1 ; J18.2 145.49,24.94 ; 132.61,130.81 DCLKQ-.4 ; DCLKQ-.4 133.86,129.56 ; DCLKQ-.4 134.79,129.88 ; DCLKQ-.4 133.86,132.06 ; DCLKQ-.4 132.93,129.88 ; DCLKQ-.4 135.1,130.81 ; DCLKQ-.4 132.93,131.74 ; DCLKQ-.4 134.79,131.74 ; J4.3 176.41,143.66 ; J4.3 175.7,143.44 ; J4.3 175.48,142.74 ; J4.3 175.7,142.03 ; J4.3 176.41,141.81 ; J4.3 177.12,142.03 ; J4.3 177.34,142.74 ; J4.3 177.12,143.44 ; J4.27 157.02,142.74 ; J4.27 156.8,142.03 ; J4.27 156.09,143.66 ; J4.27 156.8,143.44 ; J4.27 155.16,142.74 ; J4.27 156.09,141.81 ; J4.27 155.38,143.44 ; J4.27 155.38,142.03 ; 144.99,117.18 RCOUT1-.4 ; RCOUT1-.4 146.85,119.04 ; RCOUT1-.4 147.17,118.11 ; RCOUT1-.4 145.92,116.86 ; RCOUT1-.4 144.99,119.04 ; RCOUT1-.4 145.92,119.36 ; RCOUT1-.4 144.68,118.11 ; RCOUT1-.4 146.85,117.18 ; J44.8 119.02,24.94 ; J44.8 117.91,26.06 ; J44.8 116.79,24.94 ; J44.8 118.75,25.78 ; J44.8 118.75,24.1 ; J44.8 117.07,24.1 ; J44.8 117.91,23.82 ; J44.8 117.07,25.78 ; 165.54,143.44 J4.15 ; J4.15 167.18,142.74 ; J4.15 166.96,143.44 ; J4.15 165.32,142.74 ; J4.15 166.25,143.66 ; J4.15 165.54,142.03 ; J4.15 166.25,141.81 ; J4.15 166.96,142.03 ; 64.89,171.22 L9.3 ; L9.3 67.28,170.2 ; L9.3 65.69,169.89 ; L9.3 67.28,172.24 ; L9.3 65.24,170.2 ; L9.3 66.26,169.85 ; L9.3 66.26,172.59 ; L9.3 65.24,172.24 ; DCLKQ-.5 140.18,130.81 ; DCLKQ-.5 139.87,131.74 ; DCLKQ-.5 138.01,131.74 ; DCLKQ-.5 137.69,130.81 ; DCLKQ-.5 138.94,132.06 ; DCLKQ-.5 138.01,129.88 ; DCLKQ-.5 138.94,129.56 ; DCLKQ-.5 139.87,129.88 ; RCLK+.5 175.13,127.28 ; RCLK+.5 174.2,125.11 ; RCLK+.5 174.2,126.97 ; RCLK+.5 175.13,124.79 ; RCLK+.5 176.06,126.97 ; RCLK+.5 173.89,126.04 ; RCLK+.5 176.06,125.11 ; RCLK+.5 176.38,126.04 ; 161.5,130.19 RCLK-.2 ; RCLK-.2 162.43,129.87 ; RCLK-.2 163.36,132.05 ; RCLK-.2 163.68,131.12 ; RCLK-.2 163.36,130.19 ; RCLK-.2 162.43,132.36 ; RCLK-.2 161.19,131.12 ; RCLK-.2 161.5,132.05 ; 161.17,141.81 J4.21 ; J4.21 160.46,143.44 ; J4.21 162.1,142.74 ; J4.21 161.88,143.44 ; J4.21 160.46,142.03 ; J4.21 161.17,143.66 ; J4.21 161.88,142.03 ; J4.21 160.24,142.74 ; RCLK-.3 158.28,132.05 ; RCLK-.3 158.6,131.12 ; RCLK-.3 157.35,132.36 ; RCLK-.3 156.11,131.12 ; RCLK-.3 156.42,130.19 ; RCLK-.3 157.35,129.87 ; RCLK-.3 156.42,132.05 ; RCLK-.3 158.28,130.19 ; RCOUT1-.5 151.93,117.18 ; RCOUT1-.5 151,116.86 ; RCOUT1-.5 150.07,117.18 ; RCOUT1-.5 150.07,119.04 ; RCOUT1-.5 151,119.36 ; RCOUT1-.5 149.76,118.11 ; RCOUT1-.5 152.25,118.11 ; RCOUT1-.5 151.93,119.04 ; 156.11,126.04 RCLK-.4 ; RCLK-.4 157.35,127.28 ; RCLK-.4 158.6,126.04 ; RCLK-.4 156.42,125.11 ; RCLK-.4 158.28,125.11 ; RCLK-.4 157.35,124.79 ; RCLK-.4 158.28,126.97 ; RCLK-.4 156.42,126.97 ; 118.51,38.15 TP11.1 ; TP11.1 120.47,37.31 ; TP11.1 120.2,36.47 ; TP11.1 118.24,37.31 ; TP11.1 118.51,36.47 ; TP11.1 119.35,36.19 ; TP11.1 120.2,38.15 ; TP11.1 119.35,38.43 ; J18.8 139.83,25.78 ; J18.8 138.99,26.06 ; J18.8 140.11,24.94 ; J18.8 137.87,24.94 ; J18.8 138.15,25.78 ; J18.8 139.83,24.1 ; J18.8 138.99,23.82 ; J18.8 138.15,24.1 ; 125.53,23.82 J44.2 ; J44.2 125.53,26.06 ; J44.2 126.64,24.94 ; J44.2 124.69,25.78 ; J44.2 124.69,24.1 ; J44.2 126.37,25.78 ; J44.2 124.41,24.94 ; J44.2 126.37,24.1 ; 157.33,49.43 TP8.1 ; TP8.1 157.6,50.27 ; TP8.1 159.29,48.59 ; TP8.1 158.45,48.31 ; TP8.1 157.6,48.59 ; TP8.1 159.29,50.27 ; TP8.1 159.56,49.43 ; TP8.1 158.45,50.55 ; 122.15,25.78 J44.4 ; J44.4 123.83,24.1 ; J44.4 123.83,25.78 ; J44.4 121.87,24.94 ; J44.4 122.99,26.06 ; J44.4 122.15,24.1 ; J44.4 122.99,23.82 ; J44.4 124.1,24.94 ; SW1.2 129.83,6.13 ; SW1.2 129.51,7.07 ; SW1.2 129.51,5.19 ; SW1.2 128.57,4.87 ; SW1.2 127.63,5.19 ; SW1.2 128.57,7.39 ; SW1.2 127.63,7.07 ; SW1.2 127.31,6.13 ; TP9.1 131.06,145.62 ; TP9.1 131.91,145.34 ; TP9.1 131.91,143.66 ; TP9.1 132.18,144.5 ; TP9.1 130.22,145.34 ; TP9.1 131.06,143.38 ; TP9.1 130.22,143.66 ; TP9.1 129.95,144.5 ; J2.4 70.39,12.44 ; J2.4 70.64,13.75 ; J2.4 68.46,12.81 ; J2.4 69.08,12.19 ; J2.4 70.67,13.28 ; J2.4 68.43,13.28 ; J2.4 68.71,12.44 ; J2.4 69.55,12.17 ; 172.39,163.78 TP10.1 ; TP10.1 172.67,164.62 ; TP10.1 174.35,164.62 ; TP10.1 174.63,163.78 ; TP10.1 173.51,162.66 ; TP10.1 173.51,164.9 ; TP10.1 174.35,162.94 ; TP10.1 172.67,162.94 ; 162.43,124.79 RCLK-.5 ; RCLK-.5 163.36,126.97 ; RCLK-.5 161.5,126.97 ; RCLK-.5 163.68,126.04 ; RCLK-.5 162.43,127.28 ; RCLK-.5 161.5,125.11 ; RCLK-.5 163.36,125.11 ; RCLK-.5 161.19,126.04 ; 173.16,142.03 J4.6 ; J4.6 173.87,141.81 ; J4.6 172.94,142.74 ; J4.6 174.8,142.74 ; J4.6 173.87,143.66 ; J4.6 174.58,142.03 ; J4.6 174.58,143.44 ; J4.6 173.16,143.44 ; J15.1 153.35,156.2 ; J15.1 151.11,155.08 ; J15.1 152.23,157.32 ; J15.1 151.11,156.2 ; J15.1 153.35,157.32 ; J15.1 152.23,155.08 ; J15.1 153.35,155.08 ; J15.1 151.11,157.32 ; J18.4 144.91,24.1 ; J18.4 142.95,24.94 ; J18.4 145.19,24.94 ; J18.4 143.23,24.1 ; J18.4 144.91,25.78 ; J18.4 144.07,26.06 ; J18.4 143.23,25.78 ; J18.4 144.07,23.82 ; 137.69,123.19 DCLKQ+.2 ; DCLKQ+.2 138.94,121.94 ; DCLKQ+.2 140.18,123.19 ; DCLKQ+.2 138.94,124.44 ; DCLKQ+.2 139.87,124.12 ; DCLKQ+.2 138.01,124.12 ; DCLKQ+.2 138.01,122.26 ; DCLKQ+.2 139.87,122.26 ; 167.86,142.74 J4.12 ; J4.12 169.5,142.03 ; J4.12 168.79,141.81 ; J4.12 168.08,143.44 ; J4.12 169.5,143.44 ; J4.12 168.08,142.03 ; J4.12 169.72,142.74 ; J4.12 168.79,143.66 ; 157.92,143.44 J4.24 ; J4.24 159.34,143.44 ; J4.24 159.56,142.74 ; J4.24 158.63,143.66 ; J4.24 157.7,142.74 ; J4.24 159.34,142.03 ; J4.24 158.63,141.81 ; J4.24 157.92,142.03 ; J4.18 163.71,143.66 ; J4.18 163,143.44 ; J4.18 162.78,142.74 ; J4.18 164.42,143.44 ; J4.18 164.42,142.03 ; J4.18 164.64,142.74 ; J4.18 163,142.03 ; J4.18 163.71,141.81 ; 53.73,206.62 MT3.1 ; MT3.1 56.76,203.59 ; MT3.1 53.17,205.1 ; MT3.1 55.24,207.18 ; MT3.1 55.24,203.03 ; MT3.1 56.76,206.62 ; MT3.1 53.73,203.59 ; MT3.1 57.32,205.1 ; J4.9 171.33,143.66 ; J4.9 170.62,142.03 ; J4.9 172.04,143.44 ; J4.9 170.62,143.44 ; J4.9 172.26,142.74 ; J4.9 171.33,141.81 ; J4.9 170.4,142.74 ; J4.9 172.04,142.03 ; J25.6 112.94,11.93 ; J25.6 112.72,11.22 ; J25.6 112.01,12.86 ; J25.6 111.08,11.93 ; J25.6 111.3,12.64 ; J25.6 111.3,11.22 ; J25.6 112.72,12.64 ; J25.6 112.01,11 ; J18.6 142.65,24.94 ; J18.6 140.69,24.1 ; J18.6 140.41,24.94 ; J18.6 142.37,25.78 ; J18.6 141.53,23.82 ; J18.6 141.53,26.06 ; J18.6 140.69,25.78 ; J18.6 142.37,24.1 ; 141.23,157.9 TP5.1 ; TP5.1 140.95,158.74 ; TP5.1 142.91,157.9 ; TP5.1 142.07,157.62 ; TP5.1 142.91,159.58 ; TP5.1 143.19,158.74 ; TP5.1 141.23,159.58 ; TP5.1 142.07,159.86
  BOTTOM w0.102: C260.2 v1(177.01,86.64) 177.01,86.77 R211.1 ; FMC.H27 16.51,103 17.2,102.31 FMC.J26 ; C73.2 200.1,96.8 v1(200.27,96.8)
  BOTTOM w0.14: C123.2 116.22,95.24 v1(115.72,95.75)
  BOTTOM w0.254: R226.1 190.22,106.19 v1(189.72,105.69) ; v1(187.17,87.91) 186.66,87.4 R208.1 ; v1(189.69,109.47) 190.22,108.94 R223.1 ; R205.1 185.38,84.73 v1(184.69,84.04) ; R220.1 U1.Y20 v1(174.47,109.5) ; v1(179.48,109.43) 178.92,108.87 R217.1
  BOTTOM w0.305: C49.2 191,107.45 191,106.97 v1(190.99,106.96) ; R132.2 207.22,112.21 v1(207.23,112.22) ; C27.2 179.54,84.12 v1(179.53,84.13) ; C35.2 196.08,96.79 v1(196.07,96.8) 196.07,98.45 C38.2 ; v1(190.97,100.59) 190.97,102.14 C4.2 ; C79.2 v1(192.59,97.49) v1(192.59,96.19) C72.2 ; v1(121.71,80.74) 122.56,79.89 C88.2 ; v2(79.94,3.23) C69.1 v2(81.23,4.6) ; C48.2 189.69,110.55 v1(189.69,109.47) ; C19.2 184.6,104.34 v1(184.6,104.34) ; v1(136.23,105.42) 136.23,105.43 C93.2 ; C18.2 183.86,110.07 v1(183.87,110.06) ; C52.2 196.05,104.43 v1(196.07,104.42) ; C21.2 179.23,109.68 v1(179.48,109.43) ; C24.2 180.36,92.52 v1(179.65,91.81) ; 199.24,91.72 v1(199.95,91.72) ; 199.24,91.72 v1(198.6,91.72) ; 199.24,91.72 C34.2 ; C20.2 173.66,98.68 174.05,98.68 v1(174.57,98.16) ; C274.2 v1(141.61,100.75) ; C28.2 185.04,83.46 185.04,83.69 v1(184.69,84.04) ; v1(198.59,85.38) 198.64,85.44 C1.2 ; C119.2 141.82,93.89 v1(141.82,93.69) ; v1(179.54,99.33) 179.55,99.33 179.55,99.33 180.55,100.33 C23.2 ; v1(116.74,76.63) 116.74,77.42 C110.2 ; C41.2 190.99,87.89 v1(189.69,87.89) ; C259.2 v1(183.37,92.99) ; C5.2 189.69,91.59 v1(189.69,93) ; C29.2 v1(185.91,92.99) ; v1(123.73,99.76) 123.71,99.75 C272.2 ; v1(111.21,91.75) 110.74,91.75 110.19,92.3 R156.2 ; v1(192.26,108.23) 192.26,107.18 C6.2 ; R155.1 110.19,88.27 110.67,88.75 v1(111.28,88.75) ; C26.2 183.34,90.22 v1(183.34,89.2) ; v1(199.86,89.17) 199.88,89.15 200.34,89.15 C7.2 ; C124.2 C130.2 v1(121.72,89.75) ; v1(179.52,104.46) 180.65,103.33 C22.2 ; C268.2 200.1,96.64 v1(200.27,96.8) 200.13,96.95 200.13,98.14 C36.2 ; v2(81.18,6.99) R24.1 v2(79.94,8.33) ; C39.2 v1(198.64,94.22) ; C2.2 199.89,109.57 v1(199.9,109.56) ; v1(190.96,86.61) 190.96,85.54 C47.2 ; v1(131.72,100.75) C90.2 v1(131.72,101.75) ; R130.2 v1(201.03,112.21) ; v1(119.71,104.76) 119.72,104.76 C96.2 ; v1(198.62,99.35) 198.62,99.34 C40.2 ; C3.2 197.49,102.07 197.49,103.03 v1(197.35,103.17) ; C30.2 173.63,91.88 173.63,91.12 v1(174.25,90.51) ; C258.2 v1(183.37,100.6)
  BOTTOM w0.381: C125.2 v1(120.71,92.75)
  BOTTOM w0.406: v1(166.55,94.18) C364.2
  BOTTOM w0.508: v3(17.14,116.92) FMC.J38 ; FMC.J38 v3(18.41,118.19) FMC.K39 ; FMC.J38 v3(18.41,116.92) ; FMC.J38 v3(17.14,118.19) FMC.H39 ; FMC.C40 v3(10.79,120.73) ; FMC.C40 v3(10.79,119.46) FMC.D39 ; FMC.C40 v3(9.53,119.46) FMC.B39 ; FMC.C40 v3(9.53,120.73) ; v3(18.41,120.73) FMC.J40 v3(17.14,119.46) FMC.H39 ; FMC.B2 v3(9.53,72.47) FMC.B3 ; FMC.B2 v3(8.26,71.2) FMC.A1 ; FMC.B2 v3(9.53,71.2) FMC.C1 ; FMC.B2 v3(8.26,72.47) FMC.B3 ; FMC.G40 v3(14.61,119.46) FMC.F39 ; FMC.F39 v3(14.61,118.19) FMC.G38 ; FMC.F39 v3(13.34,118.19) FMC.E38 ; FMC.C38 v3(10.79,116.92) FMC.D37 ; FMC.C38 v3(10.79,118.19) FMC.D39 ; FMC.C38 v3(9.53,118.19) ; FMC.C38 v3(9.53,116.92) FMC.B38 ; FMC.F6 v3(14.61,76.28) FMC.G5 ; FMC.F6 v3(13.34,77.55) ; FMC.F6 v3(13.34,76.28) FMC.E5 v3(12.06,76.28) FMC.D6 ; D2.1 102.59,176.74 v2(102.6,176.74) ; v3(12.06,116.92) FMC.E38 ; FMC.E38 v3(13.34,116.92) ; FMC.E38 v3(12.06,118.19) FMC.D39 ; FMC.A40 v3(8.26,119.46) FMC.B39 ; FMC.A40 v3(6.99,120.73) ; FMC.A40 v3(6.99,119.46) ; FMC.A40 v3(8.26,120.73) ; FMC.B15 v3(8.26,88.98) FMC.A16 ; FMC.B15 v3(9.53,88.98) FMC.C16 ; FMC.B15 v3(8.26,87.71) FMC.B14 ; FMC.A8 v3(8.26,78.82) FMC.B7 ; FMC.A8 v3(6.99,80.09) FMC.A9 ; FMC.A8 v3(8.26,80.09) FMC.A9 ; FMC.A8 v3(6.99,78.82) ; FMC.D39 v3(12.06,119.46) FMC.E40 ; C59.2 99.35,25.43 100.25,25.43 v2(100.71,24.97) ; v3(15.88,101.68) FMC.G26 ; v3(8.26,82.63) FMC.B10 ; FMC.B10 v3(8.26,81.36) ; FMC.B10 v3(9.53,82.63) ; FMC.B10 v3(9.53,81.36) FMC.C9 v3(9.53,80.09) FMC.C8 ; FMC.B39 v3(9.53,118.19) ; FMC.B39 v3(8.26,118.19) FMC.B38 ; FMC.A16 v3(8.26,90.25) FMC.A17 ; FMC.A16 v3(6.99,90.25) FMC.A17 ; FMC.A16 v3(6.99,88.98) ; FMC.B7 v3(9.53,78.82) FMC.C8 ; FMC.B7 v3(8.26,77.55) FMC.B6 ; FMC.B7 v3(9.53,77.55) FMC.B6 ; FMC.B6 v3(9.53,76.28) FMC.C5 v3(9.53,75.01) FMC.C4 ; FMC.B6 v3(8.26,76.28) FMC.A5 ; FMC.C4 v3(9.53,73.74) FMC.B3 ; FMC.C4 v3(10.79,73.74) FMC.D3 v3(10.79,72.47) FMC.D2 ; FMC.A1 v3(6.99,71.2) ; FMC.A1 v3(8.26,69.93) ; FMC.A1 v3(6.99,69.93) ; FMC.C36 v3(10.79,114.38) ; FMC.E8 v3(12.06,78.82) FMC.D7 v3(10.79,78.82) FMC.C8 ; FMC.E8 v3(12.06,80.09) ; FMC.E8 v3(13.34,80.09) FMC.F9 v3(13.34,81.36) ; FMC.D28 v3(10.79,105.49) ; v3(10.79,105.49) FMC.C29 v3(10.79,106.76) ; v3(10.79,105.49) FMC.C28 ; FMC.C16 v3(10.79,88.98) FMC.D16 ; FMC.C16 v3(9.53,90.25) FMC.C17 ; FMC.A33 v3(6.99,110.57) FMC.A32 ; FMC.A33 v3(8.26,110.57) FMC.A32 ; FMC.A33 v3(6.99,111.84) ; FMC.K6 v3(18.41,76.28) FMC.J5 v3(17.14,76.28) FMC.H6 v3(17.14,77.55) ; FMC.K6 v3(19.68,76.28) ; FMC.K6 v3(19.68,77.55) ; FMC.A37 v3(6.99,115.65) FMC.A36 ; FMC.A37 v3(8.26,116.92) FMC.B38 ; FMC.A37 v3(8.26,115.65) FMC.A36 ; FMC.A37 v3(6.99,116.92) ; FMC.E1 v3(12.06,71.2) FMC.D2 ; FMC.E1 v3(13.34,69.93) ; FMC.E1 v3(13.34,71.2) FMC.F2 ; FMC.B3 v3(8.26,73.74) FMC.A4 ; FMC.E35 v3(13.34,114.38) FMC.F36 v3(14.61,114.38) FMC.G35 ; FMC.A12 v3(8.26,85.17) FMC.A13 ; FMC.A12 v3(6.99,83.9) ; FMC.A12 v3(6.99,85.17) FMC.A13 ; FMC.H2 v3(15.88,71.2) FMC.G1 v3(14.61,71.2) FMC.F2 ; FMC.H2 v3(15.88,72.47) FMC.H3 v3(17.14,72.47) FMC.H2 ; FMC.H2 v3(17.14,71.2) FMC.J1 v3(18.41,71.2) FMC.K2 ; v2(159.06,41.58) C163.2 v2(159.06,43.82) ; FMC.A4 v3(6.99,73.74) ; FMC.A4 v3(6.99,75.01) FMC.A5 ; FMC.A4 v3(8.26,75.01) FMC.A5 ; FMC.B14 v3(9.53,86.44) FMC.C13 v3(9.53,85.17) FMC.C12 v3(10.79,83.9) ; FMC.B14 v3(8.26,86.44) FMC.A13 ; v3(10.79,100.41) FMC.C24 v3(10.79,99.14) ; v3(10.79,100.41) FMC.C25 ; v3(10.79,100.41) FMC.D25 ; FMC.C17 v3(10.79,90.25) FMC.D16 ; FMC.C17 v3(10.79,91.52) ; FMC.C17 v3(9.53,91.52) FMC.B18 ; FMC.F15 v3(13.34,88.98) ; FMC.A21 v3(8.26,96.6) FMC.B22 ; FMC.A21 v3(6.99,96.6) ; FMC.A21 v3(6.99,95.33) FMC.A20 ; FMC.A21 v3(8.26,95.33) FMC.A20 ; FMC.G20 v3(14.61,95.33) FMC.F21 ; FMC.G20 v3(15.88,94.06) ; FMC.G20 v3(14.61,94.06) ; C66.2 85.79,37.67 v2(84.69,37.67) ; FMC.J32 v3(17.14,110.57) FMC.H33 v3(15.88,110.57) FMC.G32 ; FMC.F2 v3(14.61,72.47) FMC.F3 v3(13.34,72.47) FMC.F2 ; FMC.A25 v3(6.99,100.41) FMC.A24 ; FMC.A25 v3(8.26,101.68) FMC.B26 v3(8.26,102.95) FMC.B27 v3(8.26,104.22) FMC.A28 v3(6.99,104.22) ; FMC.A25 v3(6.99,101.68) ; FMC.A25 v3(8.26,100.41) FMC.A24 ; FMC.H36 v3(17.14,114.38) FMC.J35 ; FMC.J11 v3(18.41,83.9) FMC.K12 ; FMC.J11 v3(18.41,82.63) ; FMC.J11 v3(17.14,83.9) FMC.H12 v3(17.14,85.17) ; FMC.D19 v3(12.06,94.06) FMC.E20 ; FMC.D19 v3(10.79,94.06) FMC.C20 ; FMC.D19 v3(12.06,92.79) ; FMC.B19 v3(8.26,94.06) FMC.A20 ; FMC.B19 v3(8.26,92.79) FMC.B18 ; FMC.B19 v3(9.53,92.79) FMC.B18 ; v1(109.51,73.13) v1(110.46,73.13) ; FMC.B38 v3(9.53,118.19) ; C62.2 v2(91.04,43.84) ; FMC.D16 v3(12.06,90.25) FMC.E17 ; FMC.B18 v3(8.26,91.52) FMC.A17 ; FMC.A32 v3(6.99,109.3) ; FMC.A32 v3(8.26,109.3) FMC.B31 v3(8.26,108.03) FMC.B30 v3(8.26,106.76) FMC.A29 v3(6.99,106.76) ; FMC.A13 v3(6.99,86.44) ; v3(14.61,116.92) FMC.G38 ; FMC.G38 v3(15.88,118.19) FMC.H39 ; FMC.G38 v3(15.88,116.92) ; C55.2 83.99,31.06 84.47,31.06 v2(84.77,30.77) ; FMC.E17 v3(12.06,91.52) ; FMC.E17 v3(13.34,91.52) FMC.F18 v3(13.34,92.79) ; FMC.E17 v3(13.34,90.25) ; C65.2 86.35,34.44 v2(85.08,34.44) ; FMC.E40 v3(12.06,120.73) ; FMC.E40 v3(13.34,120.73) ; FMC.A5 v3(6.99,76.28) ; v3(17.14,100.41) FMC.H24 ; v3(12.06,85.17) FMC.D13 v3(12.06,86.44) FMC.E14 ; FMC.A20 v3(6.99,94.06) ; v3(19.68,99.14) FMC.K24 v3(18.41,99.14) FMC.J23 v3(18.41,97.87) ; FMC.J20 v3(17.14,95.33) FMC.H21 v3(17.14,96.6) ; FMC.J20 v3(18.41,94.06) ; FMC.J20 v3(18.41,95.33) FMC.K21 v3(18.41,96.6) ; R214.1 173.96,83.59 v1(174.47,84.1) ; FMC.E26 v3(13.34,102.95) FMC.F27 v3(13.34,104.22) ; v3(15.88,81.36) FMC.H9 v3(15.88,80.09) FMC.G8 v3(15.88,78.82) ; FMC.K36 v3(18.41,114.38) FMC.J35 ; FMC.K33 v3(19.68,110.57) ; FMC.A24 v3(8.26,99.14) FMC.B23 ; FMC.A24 v3(6.99,99.14) ; FMC.A36 v3(8.26,114.38) FMC.B35 v3(8.26,113.11) FMC.B34 ; FMC.A36 v3(6.99,114.38) ; v3(13.34,96.6) FMC.F21 ; FMC.F21 v3(13.34,95.33) FMC.E20 ; FMC.F21 v3(14.61,96.6) ; FMC.F12 v3(13.34,83.9) FMC.E11 v3(13.34,82.63) ; FMC.F12 v3(14.61,83.9) FMC.G11 ; FMC.F12 v3(13.34,85.17) ; FMC.E29 v3(13.34,106.76) FMC.F30 v3(14.61,106.76) FMC.G29 v3(15.88,106.76) FMC.H30 v3(17.14,106.76) FMC.J29 ; v3(10.79,111.84) FMC.C33 v3(10.79,110.57) FMC.C32 v3(10.79,109.3) ; FMC.A9 v3(6.99,81.36) ; C56.2 90.18,25.21 v2(90.2,25.19) ; FMC.F24 v3(14.61,99.14) FMC.G23 v3(15.88,97.87) ; FMC.D2 v3(10.79,71.2) FMC.C1 ; v3(13.34,94.06) FMC.E20 ; FMC.G35 v3(15.88,113.11) ; FMC.G35 v3(14.61,113.11) ; FMC.J26 v3(18.41,101.68) ; FMC.J35 v3(18.41,113.11) ; v3(8.26,83.9) FMC.B11 ; C166.2 153.15,43.61 v2(153.07,43.69) ; FMC.A17 v3(6.99,91.52) ; FMC.J8 v3(18.41,80.09) FMC.K9 ; FMC.K2 v3(19.68,72.47) FMC.K3 v3(18.41,72.47) FMC.K2 ; FMC.K2 v3(19.68,71.2) ; v3(18.41,90.25) FMC.J17 v3(18.41,91.52) FMC.K18 v3(19.68,91.52) ; v3(19.68,108.03) FMC.K30 ; v2(97.64,39.27) 97.61,39.29 97.61,39.45 98.98,40.82 C61.2 ; v3(12.06,110.57) FMC.E32 v3(13.34,110.57) FMC.F33 v3(13.34,111.84) ; FMC.G17 v3(15.88,90.25) ; FMC.K39 v3(19.68,119.46) ; FMC.K39 v3(19.68,118.19) ; C60.2 98.18,32.82 97.47,32.82 v2(97.42,32.77) ; v3(9.53,69.93) FMC.C1 ; FMC.E23 v3(12.06,97.87) FMC.D22 ; FMC.K27 v3(19.68,104.22) ; C54.2 v2(84.8,43.27)
  BOTTOM w0.61: v2(192.35,202.26) 191.53,203.08 C187.2 ; 168.53,113.6 v1(167.78,113.6) ; 168.53,115.86 v1(167.78,115.86) ; v2(190.61,203.38) 189.26,203.38 v2(189.26,202.25) ; C257.2 v1(174.47,109.5)
  BOTTOM w0.635: C323.2 126.09,25.5 J44.2 ; v1(145.06,85.17) v1(145.59,84.63) 146.94,83.29 C276.2
  BOTTOM w0.762: v1(166.34,182.65) R150.2 ; v2(117.01,176.76) 117.01,176.75 D3.1
  vias: v1(60.54,88.6) v1(64.29,61.34) v1(64.29,60.45) v1(64.29,59.59) v1(65.13,61.34) v1(65.13,60.45) v1(65.13,59.59) v1(65.96,61.32) v1(65.96,60.43) v1(65.96,59.56) v1(84.8,96.6) v1(106.15,128.55) v1(106.15,126.47) v1(108.94,128.55) v1(108.94,126.47) v1(112.66,96.74) v1(113.72,98.75) v1(113.71,93.75) v1(113.72,88.75) v1(113.69,83.75) v1(114.35,133.73) v1(114.35,131.65) v1(114.7,105.76) v1(117.14,133.73) v1(117.14,131.65) v1(117.71,104.76) v1(120.71,99.75) v1(120.71,85.74) v1(120.71,78.45) v1(121.71,105.82) v1(121.71,95.75) v1(121.71,94.75) v1(121.71,93.75) v1(121.71,92.75) v1(121.71,86.74) v1(121.78,91.75) v1(122.71,96.75) v1(122.71,87.74) v1(122.71,85.74) v1(123.74,101.75) v1(123.71,96.75) v1(124.71,86.74) v1(127.05,166.45) v1(127.05,165.56) v1(127.05,164.69) v1(128.73,166.42) v1(128.73,165.53) v1(128.73,164.67) v1(128.71,103.76) v1(128.71,97.75) v1(129.72,105.76) v1(129.72,86.74) v1(130.72,97.75) v1(130.72,96.75) v1(131.72,95.75) v1(131.72,94.75) v1(131.72,90.75) v1(131.72,89.75) v1(131.72,87.74) v1(131.72,83.74) v1(132.71,95.75) v1(132.72,93.75) v1(132.72,92.75) v1(132.72,89.75) v1(132.72,86.74) v1(132.72,85.74) v1(134.67,85.7) v1(135.49,125.99) v1(135.72,95.75) v1(135.72,80.74) v1(136.29,107.54) v1(137.72,83.74) v1(139.72,87.74) v1(141.61,86.62) v1(158.85,6.2) v1(159.86,99.09) v1(160.02,6.27) v1(162,57.96) v1(162,57.07) v1(162,56.21) v1(163.68,57.94) v1(163.68,57.05) v1(163.68,56.18) v1(170.71,6.22) v1(171.78,6.17) v1(192.18,6.27) v1(193.42,6.25) v1(199.95,95.46) v1(208.69,115.11) v1(208.74,113.94) v1(208.66,103.3) v1(208.74,102.06) v1(208.74,91.72) v1(208.69,90.42) v1(208.74,79.71) v1(208.71,43.23) v1(208.74,32.59) v1(208.81,78.41) v1(208.81,44.42) v1(208.84,15.16) v1(208.91,31.29) v1(208.91,13.69) v2(88.49,153.57) v2(88.49,152.58) v2(89.14,163.62) v2(89.14,162.1) v2(90.4,153.57) v2(90.4,152.58) v2(90.67,163.62) v2(90.67,162.1) v2(92.19,163.62) v2(92.19,162.1) v2(108.97,192.36) v2(108.97,190.84) v2(110.5,192.36) v2(110.5,190.84) v2(128.79,191.11) v2(128.79,189.58) v2(130.31,191.11) v2(130.31,189.58) v2(131.83,191.11) v2(131.83,189.58) v2(151.94,186.27) v2(153.88,196.93) v2(153.88,195.4) v2(153.88,193.88) v2(153.88,190.83) v2(153.88,189.31) v2(153.88,187.78) v2(154.45,4.47) v2(154.46,2.92) v2(154.46,1.32) v2(155.4,196.93) v2(155.4,195.4) v2(155.4,193.88) v2(155.4,190.83) v2(155.4,189.31) v2(155.4,187.78) v2(155.85,4.5) v2(155.85,2.95) v2(155.85,1.35) v2(156.92,196.93) v2(156.92,195.4) v2(156.92,193.88) v2(156.92,190.83) v2(156.92,189.31) v2(156.92,187.78) v2(159.97,196.93) v2(159.97,195.4) v2(159.97,193.88) v2(159.97,190.83) v2(159.97,189.31) v2(159.97,187.78) v2(161.5,196.93) v2(161.5,195.4) v2(161.5,193.88) v2(161.5,190.83) v2(161.5,189.31) v2(161.5,187.78) v2(163.02,196.93) v2(163.02,195.4) v2(163.02,193.88) v2(163.02,190.83) v2(163.02,189.31) v2(163.02,187.78) v2(163.04,4.47) v2(163.04,2.92) v2(163.04,1.32) v2(164.43,4.5) v2(164.44,2.95) v2(164.44,1.35) v2(164.67,186.3) v2(164.93,202.68) v2(164.93,201.41) v2(166.2,202.68) v2(166.2,201.41) v2(166.31,4.47) v2(166.32,2.92) v2(166.32,1.32) v2(167.71,4.5) v2(167.72,2.95) v2(167.72,1.35) v2(174.8,4.47) v2(174.8,2.92) v2(174.8,1.32) v2(176.19,4.5) v2(176.2,2.95) v2(176.2,1.35) v2(180.25,202.84) v2(180.25,201.57) v2(181.52,202.84) v2(181.52,201.57) v2(187.73,4.47) v2(187.73,2.92) v2(187.73,1.32) v2(189.12,4.5) v2(189.13,2.95) v2(189.13,1.35) v2(196.44,4.52) v2(196.44,2.97) v2(196.44,1.37) v2(196.77,202.65) v2(196.77,201.38) v2(197.84,4.55) v2(197.84,3) v2(197.84,1.4) v2(198.04,202.65) v2(198.04,201.38) v2(210.36,184.94) v2(210.39,183.54) v2(210.44,176.25) v2(210.41,134.82) v2(210.44,133.43) v2(210.36,126.29) v2(210.39,124.89) v2(210.41,119.56) v2(210.44,118.16) v2(210.41,107.75) v2(210.44,106.35) v2(210.41,99.21) v2(210.44,97.82) v2(210.36,95.96) v2(210.39,94.56) v2(210.36,87.38) v2(210.39,85.98) v2(210.41,84.15) v2(210.44,82.75) v2(210.41,48.82) v2(210.44,47.42) v2(210.41,40.18) v2(210.44,38.79) v2(210.41,28.4) v2(210.44,27) v2(210.41,10.79) v2(210.44,9.4) v2(210.46,174.85) v2(210.52,147.02) v2(210.54,145.62) v2(210.46,138.3) v2(210.49,136.91) v2(210.46,110.92) v2(210.49,109.52) v2(210.46,75.56) v2(210.49,74.17) v2(210.54,19.43) v2(210.59,36.98) v2(210.62,35.59) v2(210.57,18.03) v2(211.96,184.94) v2(211.99,183.54) v2(212.04,176.25) v2(212.01,134.82) v2(212.04,133.43) v2(211.96,126.29) v2(211.99,124.89) v2(212.01,119.56) v2(212.04,118.16) v2(212.01,107.75) v2(212.04,106.35) v2(212.01,99.21) v2(212.04,97.82) v2(211.96,95.96) v2(211.99,94.56) v2(211.96,87.38) v2(211.99,85.98) v2(212.01,84.15) v2(212.04,82.75) v2(212.01,48.82) v2(212.04,47.42) v2(212.01,40.18) v2(212.04,38.79) v2(212.01,28.4) v2(212.04,27) v2(212.01,10.79) v2(212.04,9.4) v2(212.06,174.85) v2(212.12,147.02) v2(212.14,145.62) v2(212.06,138.3) v2(212.09,136.91) v2(212.06,110.92) v2(212.09,109.52) v2(212.06,75.56) v2(212.09,74.17) v2(212.14,19.43) v2(212.19,36.98) v2(212.22,35.59) v2(212.17,18.03) v2(213.51,184.94) v2(213.54,183.55) v2(213.51,126.29) v2(213.54,124.9) v2(213.51,95.97) v2(213.54,94.57) v2(213.51,87.38) v2(213.54,85.98) v2(213.59,176.26) v2(213.61,174.86) v2(213.61,138.31) v2(213.64,136.91) v2(213.56,134.83) v2(213.59,133.43) v2(213.56,119.56) v2(213.59,118.17) v2(213.61,110.93) v2(213.64,109.53) v2(213.56,107.75) v2(213.59,106.35) v2(213.56,99.22) v2(213.59,97.82) v2(213.56,84.16) v2(213.59,82.76) v2(213.61,75.57) v2(213.64,74.17) v2(213.56,48.82) v2(213.59,47.43) v2(213.56,40.19) v2(213.59,38.79) v2(213.56,28.4) v2(213.59,27.01) v2(213.56,10.8) v2(213.59,9.4) v2(213.66,147.02) v2(213.69,145.62) v2(213.74,36.99) v2(213.69,19.44) v2(213.72,18.04) v2(213.77,35.59) v3(6.99,105.49) v3(8.26,105.49) v3(10.16,95.96) v3(11.43,81.99) v3(12.7,74.37) v3(15.24,87.07) v3(15.24,74.37) v3(16.51,92.15) v3(16.51,88.34) v3(17.78,87.07) v3(17.78,74.37) v3(19.05,88.34) v4(191.44,158.14) v4(191.77,157.3) v4(191.77,156.54) v4(191.77,155.78) v4(191.77,155.02) v4(192.53,157.3) v4(192.53,156.54) v4(192.53,155.78) v4(192.53,155.02) v4(193.29,157.3) v4(193.29,156.54) v4(193.29,155.78) v4(193.29,155.02) v4(194.06,157.3) v4(194.06,156.54) v4(194.06,155.78) v4(194.06,155.02) v4(194.26,158.17) v4(194.82,157.3) v4(194.82,156.54) v4(194.82,155.78) v4(195.12,158.14)
